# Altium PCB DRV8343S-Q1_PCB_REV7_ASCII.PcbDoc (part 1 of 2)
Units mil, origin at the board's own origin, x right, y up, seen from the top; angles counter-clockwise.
Board outline 3860 x 4000 mil, 4 copper layers (Top Layer, POWER, GND, Bottom Layer), stack 40 mil thick; 195 components, 122 nets, 548 pads, 642 vias.
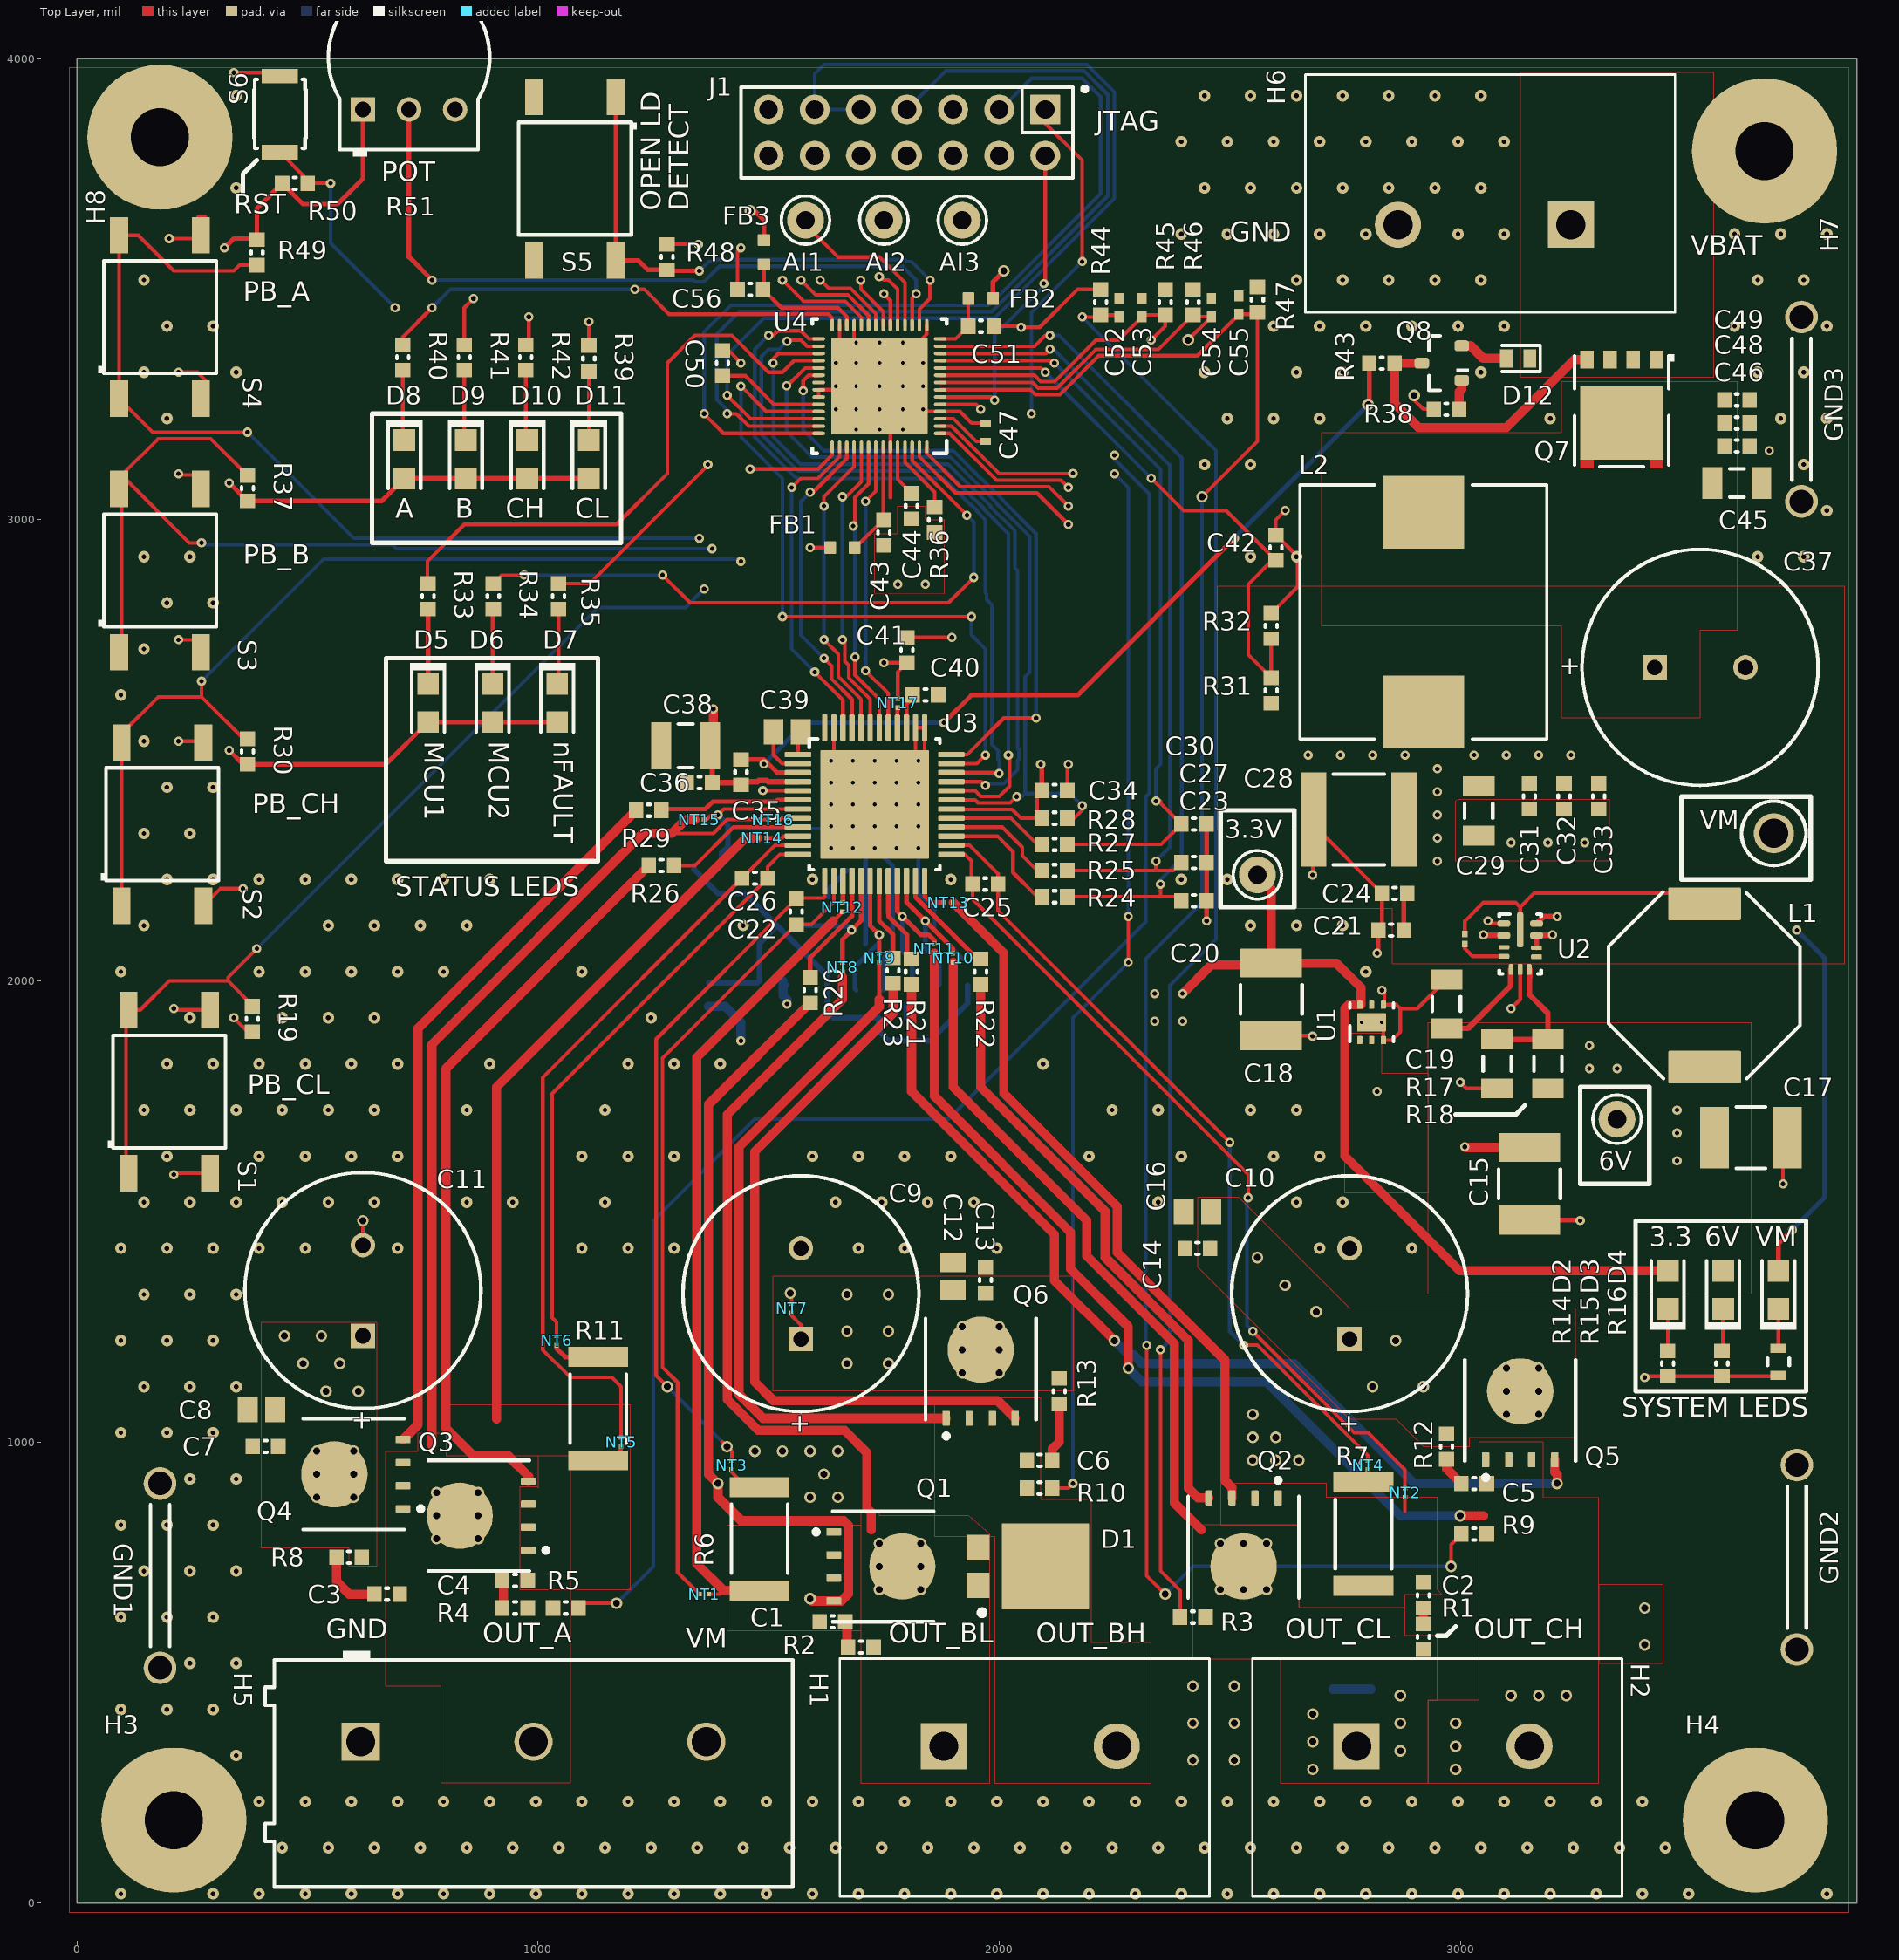
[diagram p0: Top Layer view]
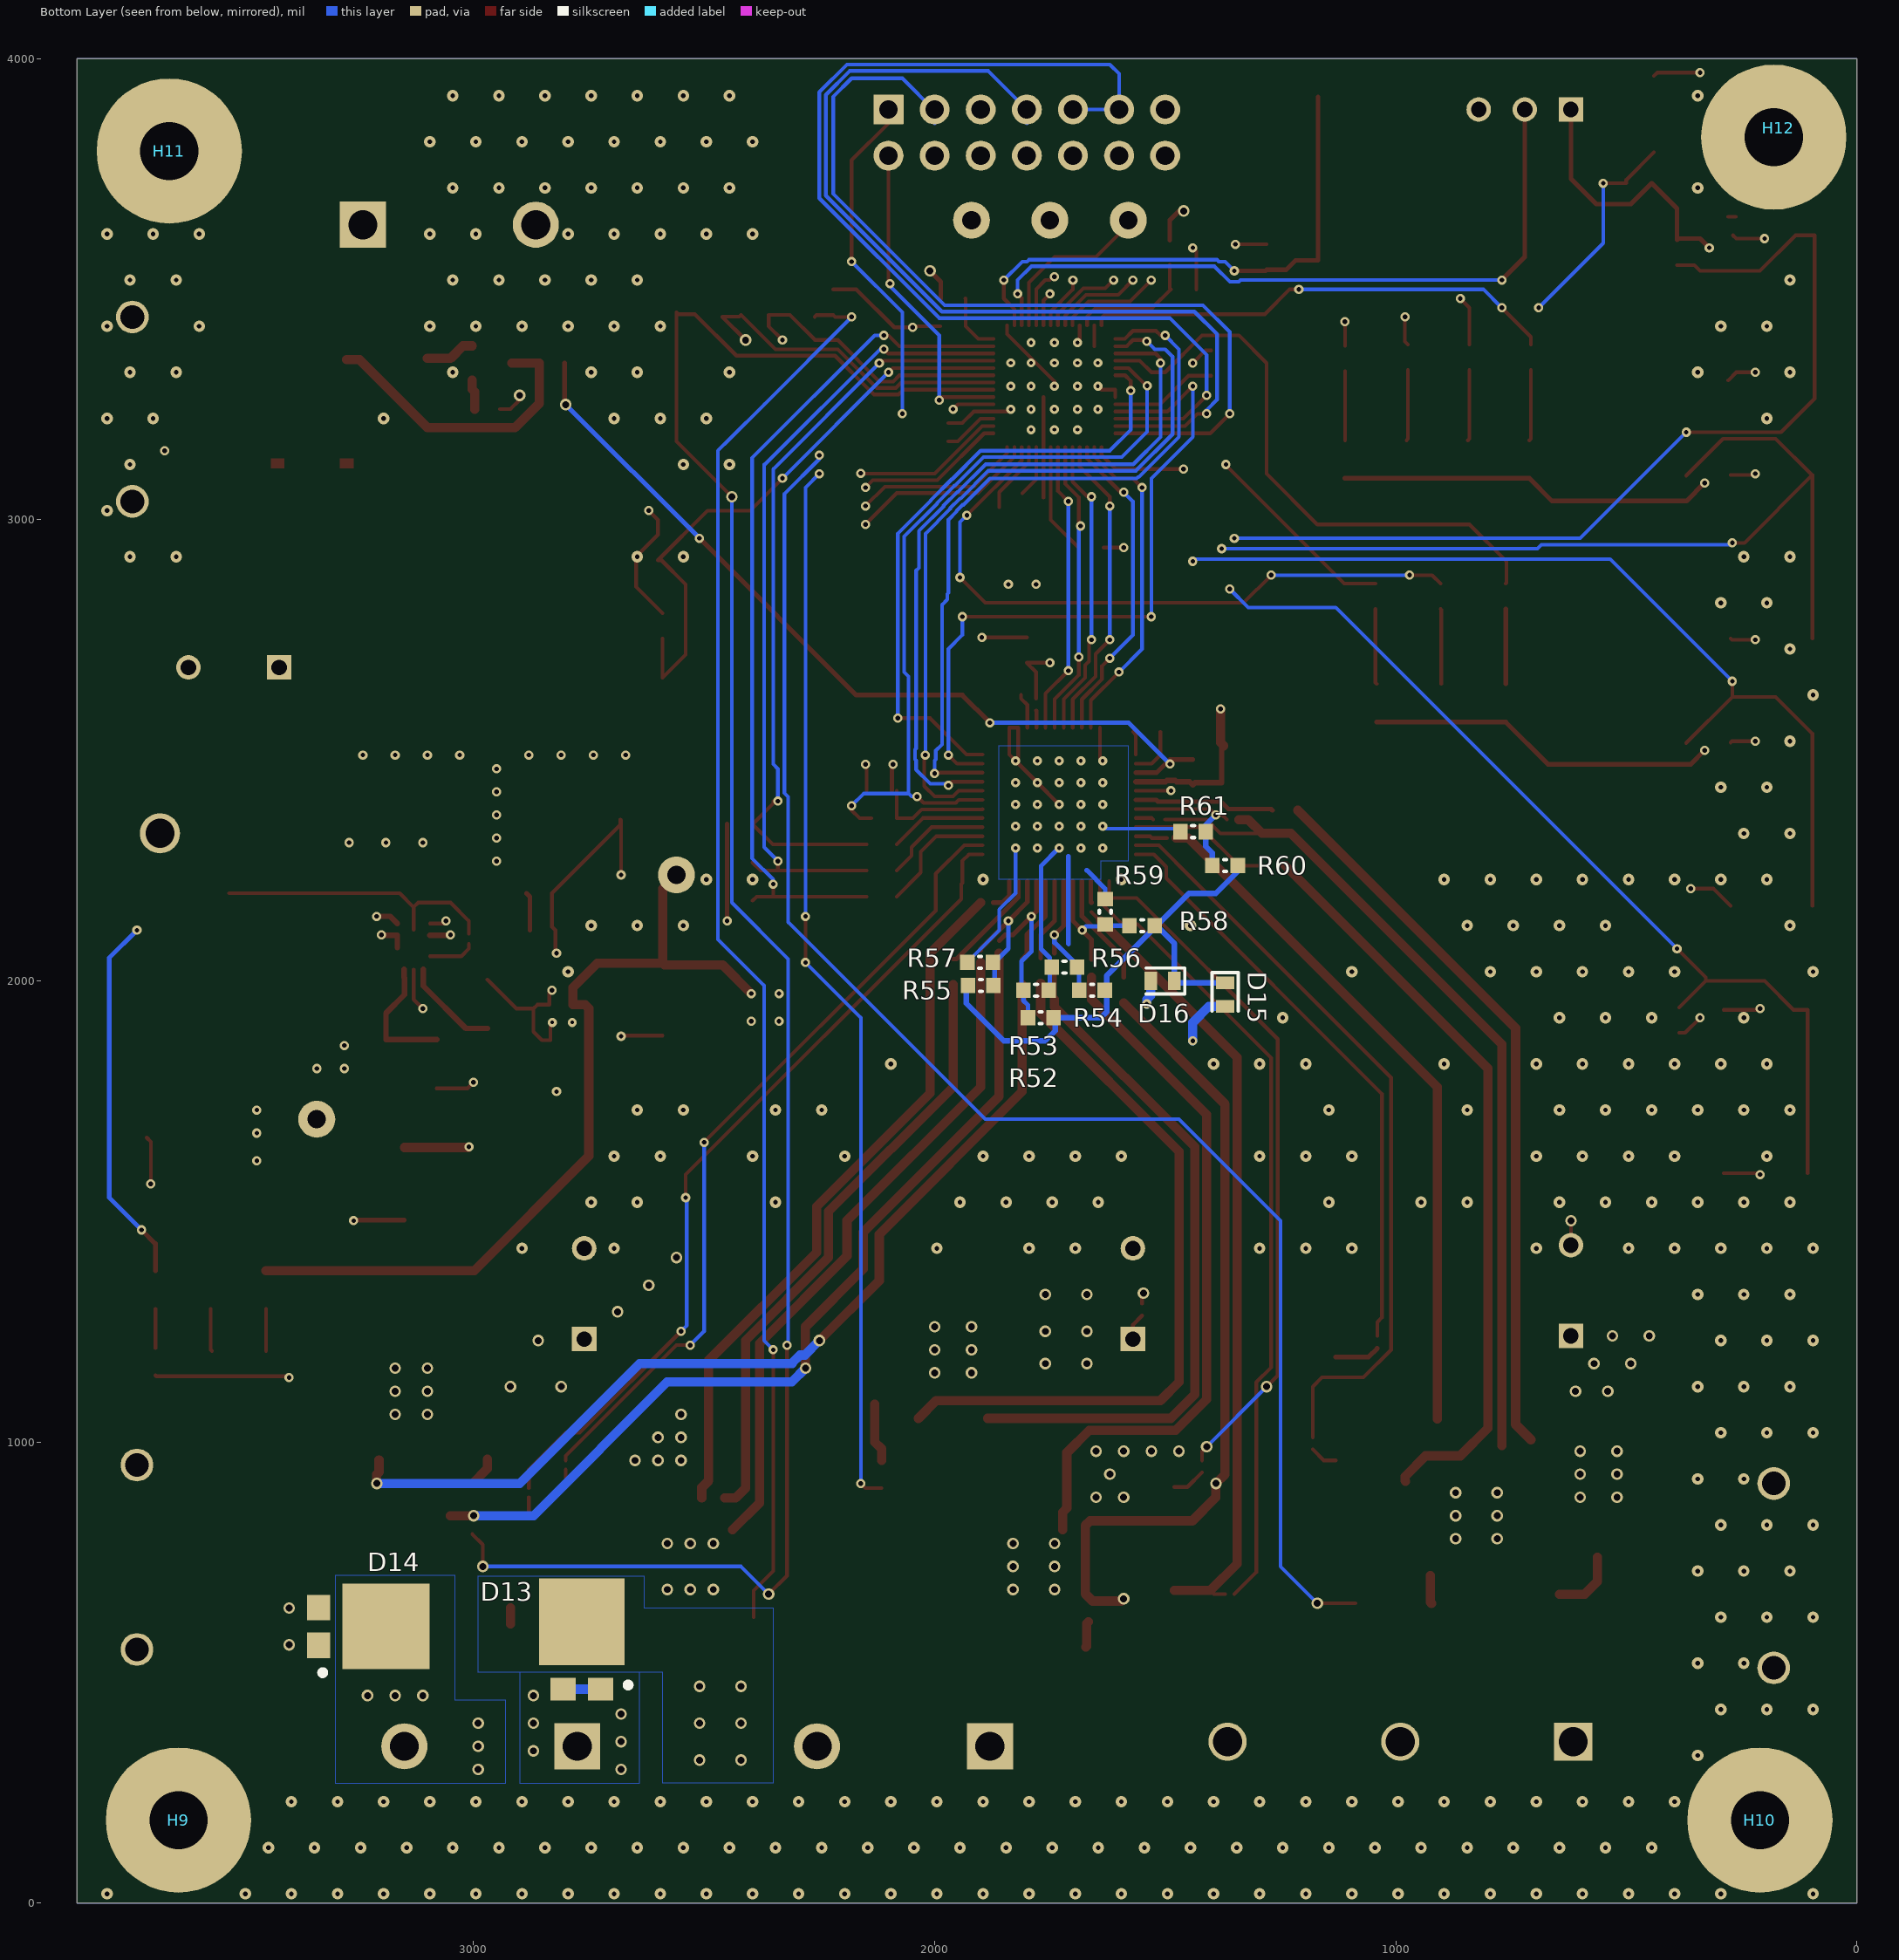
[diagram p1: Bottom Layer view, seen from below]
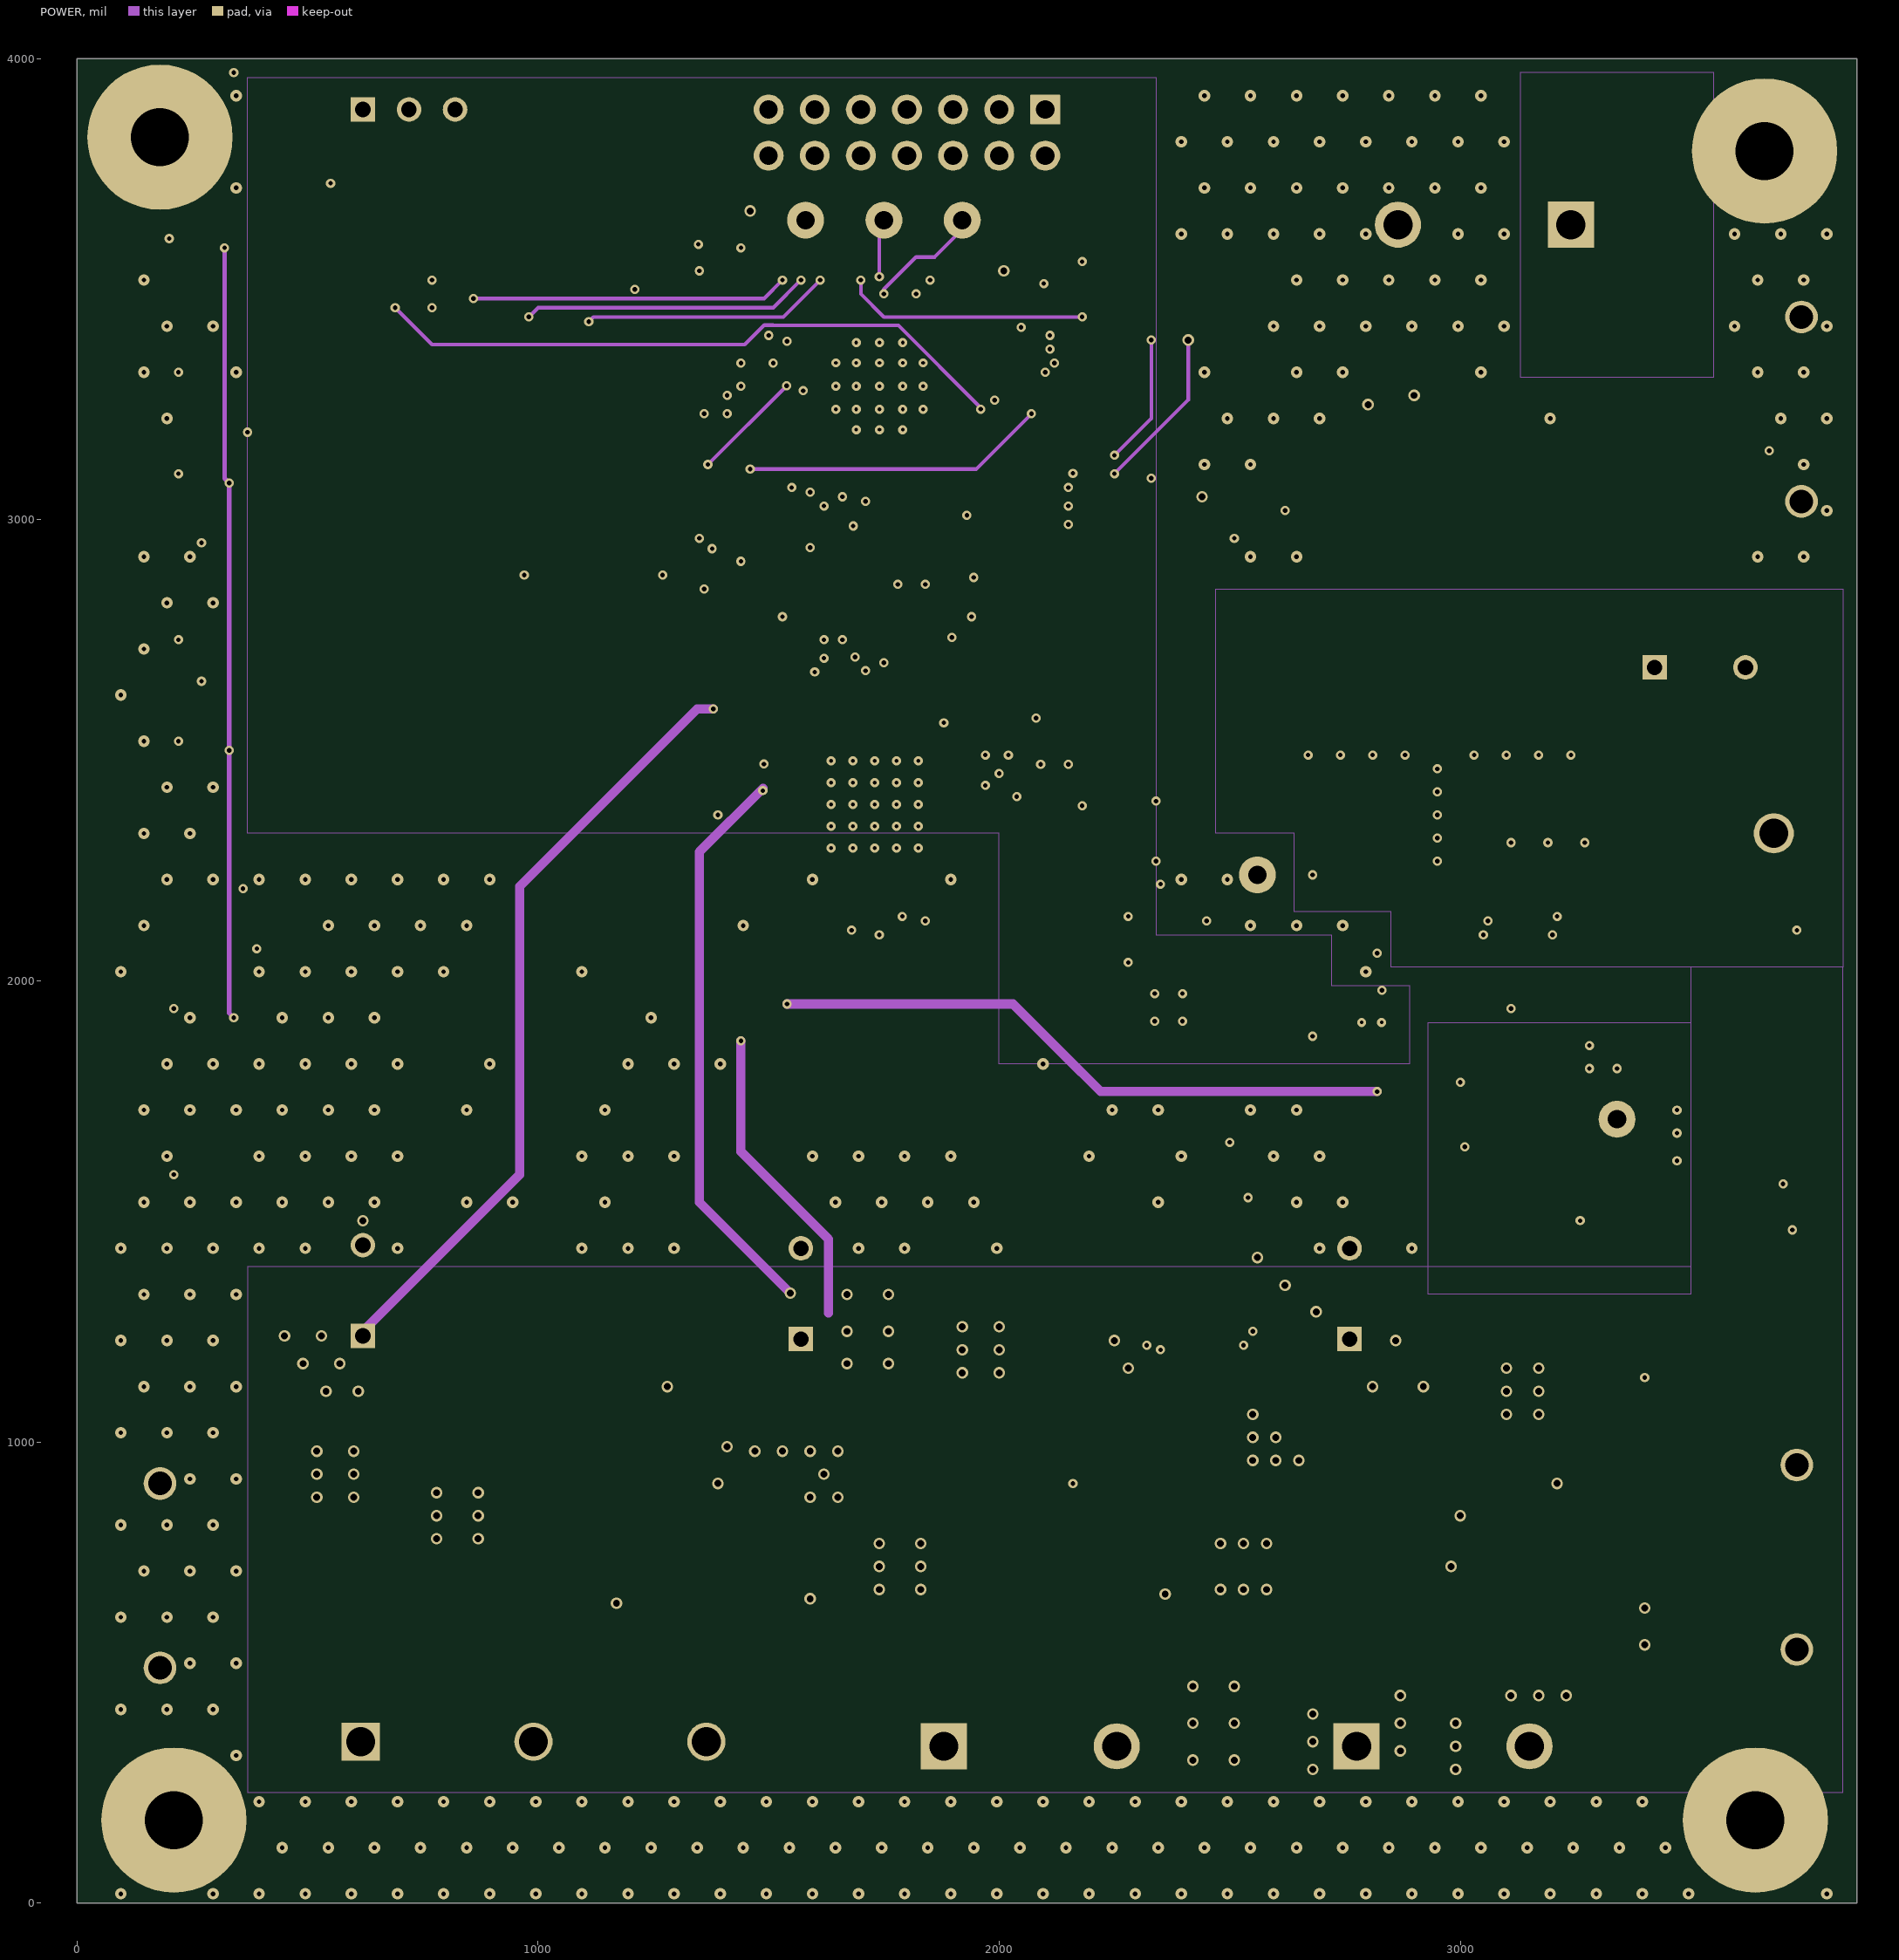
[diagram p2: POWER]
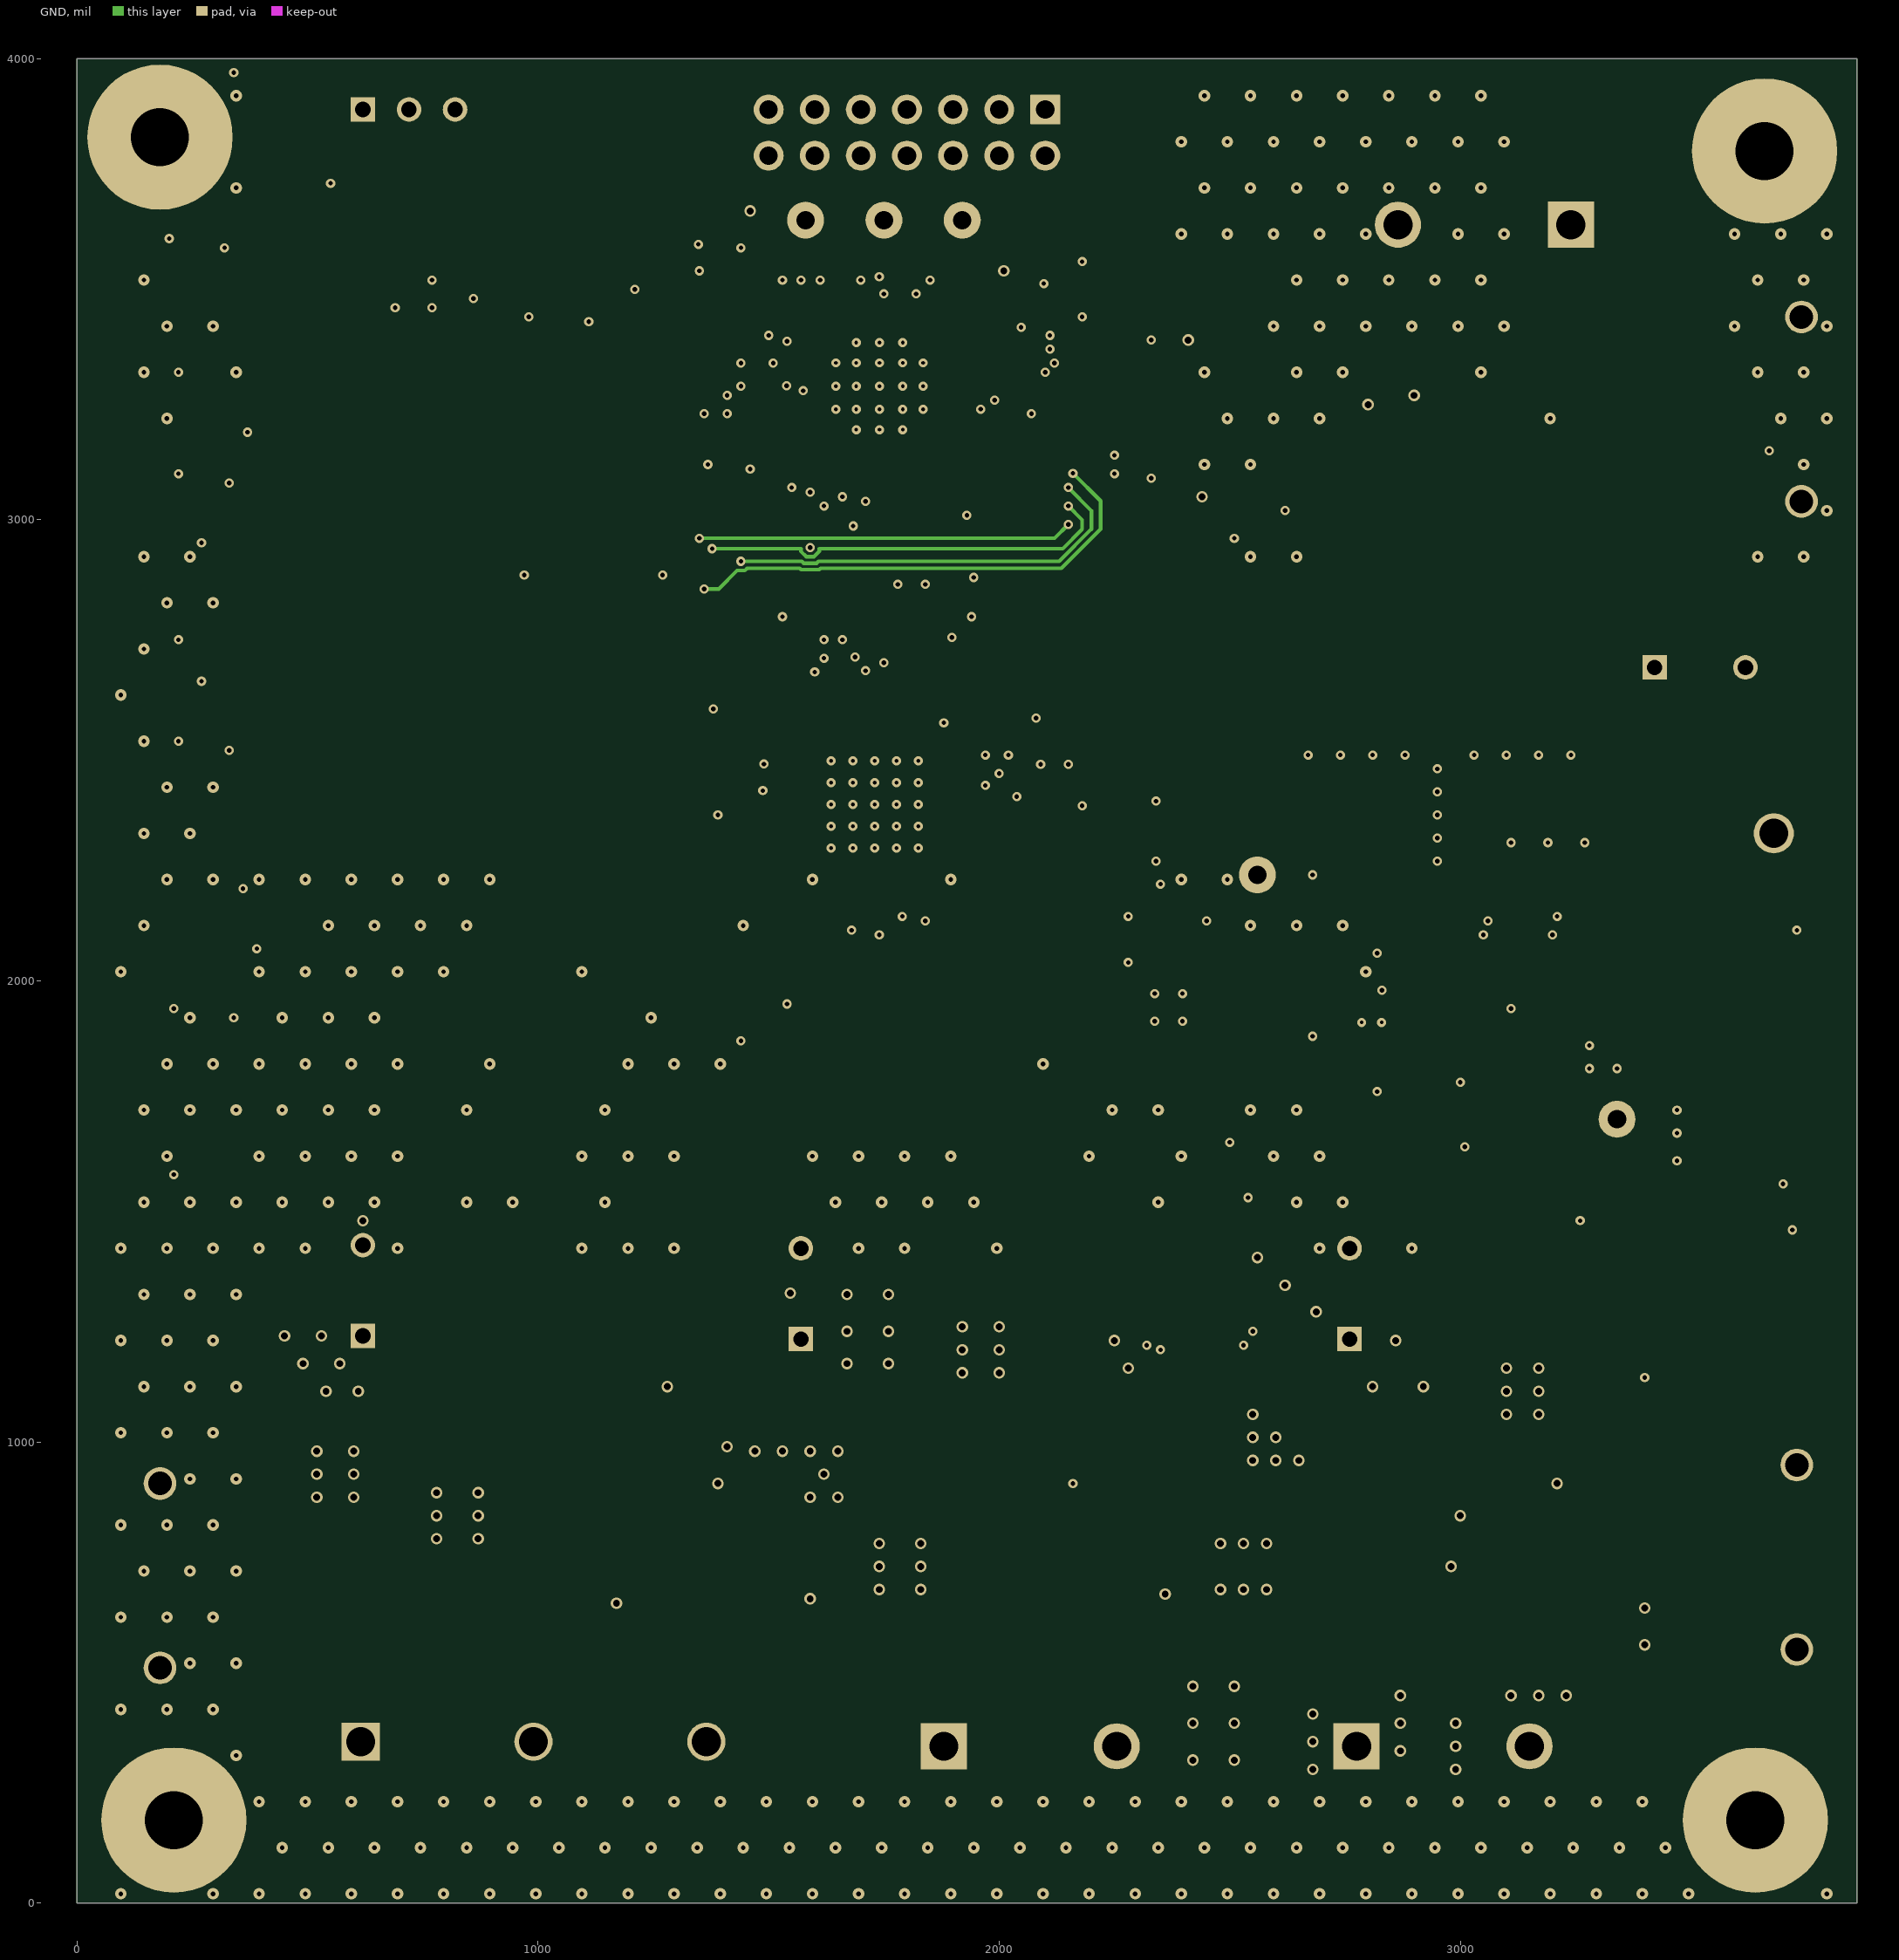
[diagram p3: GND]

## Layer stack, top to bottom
Top Solder: solder mask 0.4, Solder Resist, Dk 3.5
Top Layer: signal copper 1.4
Dielectric 1: prepreg 5, FR-4, Dk 4.2
POWER: signal copper 1.4
Dielectric 2: core 24.4, FR-4, Dk 4.2
GND: signal copper 1.4
Dielectric 3: prepreg 5, FR-4, Dk 4.2
Bottom Layer: signal copper 1.4
Bottom Solder: solder mask 0.4, Solder Resist, Dk 3.5

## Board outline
0,0 0,4000 3860,4000 3860,0

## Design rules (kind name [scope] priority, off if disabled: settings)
AssemblyTestPointUsage [All] p0 off: scope1count=1 scope1_0_kind=Board scope1_0_value=Board scope2count=1 scope2_0_kind=Board scope2_0_value=Board commentlength=0
AssemblyTestPointUsage [All] p1 off:
AssemblyTestpoint [All] p0 off: scope1count=1 scope1_0_kind=Board scope1_0_value=Board scope2count=1 scope2_0_kind=Board scope2_0_value=Board commentlength=0
AssemblyTestpoint [All] p1 off: testpointundercomponent=TRUE minsize=40 maxsize=100 preferedsize=60 minholesize=0 maxholesize=40 preferedholesize=32 testpointgrid=1 usegrid=TRUE gridtolerance=0.01 allowsidetop=TRUE allowsidebottom=TRUE
Clearance [All] p0: scope1count=1 scope1_0_kind=Board scope1_0_value=Board scope2count=1 scope2_0_kind=Board scope2_0_value=Board commentlength=0 gap=6
Clearance [All] p1: gap=6 ignorepadtopadclearanceinfootprint=FALSE except(0: Arc-Hole Track-Hole SMDPad-Hole THPad-Hole Via-Hole Fill-Hole Poly-Hole Region-Hole Text-Hole)
ComponentClearance [All] p0 off: scope1count=1 scope1_0_kind=Board scope1_0_value=Board scope2count=1 scope2_0_kind=Board scope2_0_value=Board commentlength=0 gap=10 collisioncheckmode=3
ComponentClearance [All] p1 off: gap=10 collisioncheckmode=3 verticalgap=10 showdistances=FALSE
DiffPairsRouting [All] p0 off: scope1count=1 scope1_0_kind=Board scope1_0_value=Board scope2count=1 scope2_0_kind=Board scope2_0_value=Board commentlength=0
DiffPairsRouting [All] p1 off: maxlimit=10 minlimit=10 mostfreqgap=10 toplayer_minwidth=15 toplayer_maxwidth=15 toplayer_prefwidth=15 midlayer1_minwidth=15 midlayer1_maxwidth=15 midlayer1_prefwidth=15 midlayer2_minwidth=15 midlayer2_maxwidth=15 midlayer2_prefwidth=15 bottomlayer_minwidth=15 bottomlayer_maxwidth=15 bottomlayer_prefwidth=15 maxuncoupledlength=500
FabricationTestPointUsage TestPointUsage [All] p0 off: scope1count=1 scope1_0_kind=Board scope1_0_value=Board scope2count=1 scope2_0_kind=Board scope2_0_value=Board commentlength=0 valid=0 allowmultiple=FALSE
FabricationTestPointUsage TestPointUsage [All] p1 off: valid=0 allowmultiple=FALSE
FabricationTestpoint Testpoint [All] p0 off: scope1count=1 scope1_0_kind=Board scope1_0_value=Board scope2count=1 scope2_0_kind=Board scope2_0_value=Board commentlength=0 side=3 testpointundercomponent=TRUE minsize=40 maxsize=100 preferedsize=60 minholesize=0 maxholesize=40 preferedholesize=32 testpointgrid=1
FabricationTestpoint Testpoint [All] p1 off: side=3 testpointundercomponent=TRUE minsize=40 maxsize=100 preferedsize=60 minholesize=0 maxholesize=40 preferedholesize=32 testpointgrid=1 allowsidetop=TRUE allowsidebottom=TRUE usegrid=TRUE gridtolerance=0.01
FanoutControl Fanout_Default [All] p0 off: scope1count=1 scope1_0_kind=Board scope1_0_value=Board scope2count=1 scope2_0_kind=Board scope2_0_value=Board commentlength=30 // Fanout_Default (Default Rule)
FanoutControl Fanout_Small [All] p0 off: scope1count=1 scope1_0_kind=Board scope1_0_value=Board scope2count=1 scope2_0_kind=Board scope2_0_value=Board commentlength=84 // Protel DXP Scope 1 Expression Was: (CompPinCount < 5)   Fanout_Small (Default Rule)
FanoutControl Fanout_SOIC [All] p0 off: scope1count=1 scope1_0_kind=Board scope1_0_value=Board scope2count=1 scope2_0_kind=Board scope2_0_value=Board commentlength=71 // Protel DXP Scope 1 Expression Was: IsSOIC   Fanout_SOIC (Default Rule)
FanoutControl Fanout_LCC [All] p0 off: scope1count=1 scope1_0_kind=Board scope1_0_value=Board scope2count=1 scope2_0_kind=Board scope2_0_value=Board commentlength=69 // Protel DXP Scope 1 Expression Was: IsLCC   Fanout_LCC (Default Rule)
FanoutControl Fanout_BGA [All] p0 off: scope1count=1 scope1_0_kind=Board scope1_0_value=Board scope2count=1 scope2_0_kind=Board scope2_0_value=Board commentlength=69 // Protel DXP Scope 1 Expression Was: IsBGA   Fanout_BGA (Default Rule)
FanoutControl Fanout_BGA [IsBGA] p1 off: bgadir=Out bgaviamode=Centered fanoutstyle=Auto fanoutdirection=Alternating viagrid=1 // Fanout_BGA (Default Rule)
FanoutControl Fanout_LCC [IsLCC] p2 off: bgadir=Out bgaviamode=Centered fanoutstyle=Auto fanoutdirection=Alternating viagrid=1 // Fanout_LCC (Default Rule)
FanoutControl Fanout_SOIC [IsSOIC] p3 off: bgadir=Out bgaviamode=Centered fanoutstyle=Auto fanoutdirection=Alternating viagrid=1 // Fanout_SOIC (Default Rule)
FanoutControl Fanout_Small [(CompPinCount < 5)] p4 off: bgadir=Out bgaviamode=Centered fanoutstyle=Auto fanoutdirection=OutThenIn viagrid=1 // Fanout_Small (Default Rule)
FanoutControl Fanout_Default [All] p5 off: bgadir=Out bgaviamode=Centered fanoutstyle=Auto fanoutdirection=Alternating viagrid=1 // Fanout_Default (Default Rule)
Height [All] p0 off: scope1count=1 scope1_0_kind=Board scope1_0_value=Board scope2count=1 scope2_0_kind=Board scope2_0_value=Board commentlength=0
Height [All] p1 off: minheight=0 maxheight=1000 prefheight=500
HoleSize [All] p0: scope1count=1 scope1_0_kind=Board scope1_0_value=Board scope2count=1 scope2_0_kind=Board scope2_0_value=Board commentlength=0 absolutevalues=TRUE maxlimit=400 minlimit=7.87 maxpercent=80.000 minpercent=20.000
HoleSize [All] p1: absolutevalues=TRUE maxlimit=400 minlimit=7.87 maxpercent=80.000 minpercent=20.000
HoleToHoleClearance [All] p0: scope1count=1 scope1_0_kind=Board scope1_0_value=Board scope2count=1 scope2_0_kind=Board scope2_0_value=Board commentlength=0
HoleToHoleClearance [All] p1: gap=8 allowstackedmicrovias=TRUE
LayerPairs [All] p0 off: scope1count=1 scope1_0_kind=Board scope1_0_value=Board scope2count=1 scope2_0_kind=Board scope2_0_value=Board commentlength=0 enforce=FALSE
LayerPairs [All] p1 off: enforce=FALSE
MinimumAnnularRing [All] p0: scope1count=1 scope1_0_kind=Board scope1_0_value=Board scope2count=1 scope2_0_kind=Board scope2_0_value=Board commentlength=0 minimumring=5
MinimumAnnularRing [All] p1: minimumring=5
MinimumSolderMaskSliver [All] p0: scope1count=1 scope1_0_kind=Board scope1_0_value=Board scope2count=1 scope2_0_kind=Board scope2_0_value=Board commentlength=0
MinimumSolderMaskSliver [All] p1: minsoldermaskwidth=4
NetAntennae [All] p0: scope1count=1 scope1_0_kind=Board scope1_0_value=Board scope2count=1 scope2_0_kind=Board scope2_0_value=Board commentlength=0
PasteMaskExpansion [All] p0: scope1count=1 scope1_0_kind=Board scope1_0_value=Board scope2count=1 scope2_0_kind=Board scope2_0_value=Board commentlength=0 expansion=0
PlaneClearance [All] p0: scope1count=1 scope1_0_kind=Board scope1_0_value=Board scope2count=1 scope2_0_kind=Board scope2_0_value=Board commentlength=0 clearance=20
PlaneConnect [All] p0: scope1count=1 scope1_0_kind=Board scope1_0_value=Board scope2count=1 scope2_0_kind=Board scope2_0_value=Board commentlength=0 planeconnectstyle=Relief reliefexpansion=20 reliefentries=4 reliefconductorwidth=10 reliefairgap=10
PolygonConnect [All] p0: scope1count=1 scope1_0_kind=Board scope1_0_value=Board scope2count=1 scope2_0_kind=Board scope2_0_value=Board commentlength=0 connectstyle=Direct reliefconductorwidth=25 reliefentries=4 polygonreliefangle="90 Angle"
PolygonConnect [All] p1: connectstyle=Direct reliefconductorwidth=25 reliefentries=4 polygonreliefangle="90 Angle" airgapwidth=10
RoutingCorners [All] p0: scope1count=1 scope1_0_kind=Board scope1_0_value=Board scope2count=1 scope2_0_kind=Board scope2_0_value=Board commentlength=0 cornerstyle=45-Degree minsetback=100 maxsetback=100
RoutingLayers [All] p0: scope1count=1 scope1_0_kind=Board scope1_0_value=Board scope2count=1 scope2_0_kind=Board scope2_0_value=Board commentlength=0 top layer=Automatic mid layer 1=Automatic mid layer 2=Automatic bottom layer=Automatic
RoutingPriority [All] p0: scope1count=1 scope1_0_kind=Board scope1_0_value=Board scope2count=1 scope2_0_kind=Board scope2_0_value=Board commentlength=0
RoutingTopology [All] p0: scope1count=1 scope1_0_kind=Board scope1_0_value=Board scope2count=1 scope2_0_kind=Board scope2_0_value=Board commentlength=0 topology=Shortest
RoutingVias [All] p0: scope1count=1 scope1_0_kind=Board scope1_0_value=Board scope2count=1 scope2_0_kind=Board scope2_0_value=Board commentlength=0 holewidth=15 width=25 viastyle="Through Hole" minholewidth=7.87 minwidth=18 maxholewidth=400 maxwidth=500
RoutingVias [All] p1: holewidth=15 width=25 viastyle="Through Hole" minholewidth=7.87 minwidth=18 maxholewidth=400 maxwidth=500
ShortCircuit [All] p0: scope1count=1 scope1_0_kind=Board scope1_0_value=Board scope2count=1 scope2_0_kind=Board scope2_0_value=Board commentlength=0 allowed=FALSE
SilkToBoardRegionClearance [All] p0: scope1count=1 scope1_0_kind=Board scope1_0_value=Board scope2count=1 scope2_0_kind=Board scope2_0_value=Board commentlength=0
SilkToSilkClearance [All] p0: scope1count=1 scope1_0_kind=Board scope1_0_value=Board scope2count=1 scope2_0_kind=Board scope2_0_value=Board commentlength=0
SilkToSilkClearance [All] p1: silktosilkclearance=5
SilkToSolderMaskClearance SilkscreenOverComponentPads [All] p0 off: scope1count=1 scope1_0_kind=Board scope1_0_value=Board scope2count=1 scope2_0_kind=Board scope2_0_value=Board commentlength=44 // Protel DXP Scope 1 Expression Was: IsPad
SilkToSolderMaskClearance SilkscreenOverComponentPads [IsPad] p1: minsilkscreentomaskgap=5 clearancetoexposedcopper=TRUE
SolderMaskExpansion [All] p0: scope1count=1 scope1_0_kind=Board scope1_0_value=Board scope2count=1 scope2_0_kind=Board scope2_0_value=Board commentlength=0 expansion=2
SolderMaskExpansion [All] p1: expansion=2
UnRoutedNet [All] p0: scope1count=1 scope1_0_kind=Board scope1_0_value=Board scope2count=1 scope2_0_kind=Board scope2_0_value=Board commentlength=0
UnpouredPolygon [All] p0: scope1count=1 scope1_0_kind=Board scope1_0_value=Board scope2count=1 scope2_0_kind=Board scope2_0_value=Board commentlength=0
Width [All] p0: scope1count=1 scope1_0_kind=Board scope1_0_value=Board scope2count=1 scope2_0_kind=Board scope2_0_value=Board commentlength=0 maxlimit=50 minlimit=8 preferedwidth=8
Width [All] p1: maxlimit=50 minlimit=8 preferedwidth=8
12 further rules are at their usual default settings.

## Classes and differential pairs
component class TIDA_CONTROL: Ai0 AI2 AI3 D1 D2 D3 D5 D6 D7 D8 D9 D10 D12 D16 GND1 GND2 GND3 J1 R1 R5 R7 R11 R13 R14 R15 R26 R27 R30 R31 R32 R34 R35 R37 R48 R49 R50 R51 S1 S2 S3 S4 S5 S6 U3

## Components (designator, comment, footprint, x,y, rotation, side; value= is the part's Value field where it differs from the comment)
3.3V "5000" Keystone5000 2560,2230 r90 top (schematic designator TP7)
6V "5000" Keystone5000 3340,1700 r90 top (schematic designator TP13)
AI1 "" Keystone5002 1580,3650 r90 top (schematic designator TP1)
AI2 "" Keystone5002 1750,3650 r90 top (schematic designator TP2)
AI3 "" Keystone5002 1920,3650 r90 top (schematic designator TP3)
C1 "GRM188R72A103KA01D" 0603L 1638.59,609.92 r180 top (schematic designator C52)
C2 "GRM188R72A103KA01D" 0603L 2920,667.56 r90 top (schematic designator C51)
C3 "GRM188R72A103KA01D" 0603L 672.44,670 r0 top (schematic designator C49)
C4 "GRM188R72A103KA01D" 0603L 950,700 r0 top (schematic designator C50)
C5 "GRM188R72A103KA01D" 0603L 3030,910 r0 top (schematic designator C48)
C6 "GRM188R72A103KA01D" 0603L 2087.56,960 r180 top (schematic designator C47)
C7 "06031C103JAT2A" 0603L 408.86,990 r180 top (schematic designator C39)
C8 "CGA4J3X7S2A105K125AB" 0805L 400,1070 r180 top (schematic designator C38)
C9 "ELXZ630ELL331MK20S" Chemi-Con_1250x2000 1570,1321.57 r90 top (schematic designator C45)
C10 "ELXZ630ELL331MK20S" Chemi-Con_1250x2000 2760,1321.57 r90 top (schematic designator C46)
C11 "ELXZ630ELL331MK20S" Chemi-Con_1250x2000 620,1328.43 r90 top (schematic designator C44)
C12 "CGA4J3X7S2A105K125AB" 0805L 1900,1360 r90 top (schematic designator C40)
C13 "06031C103JAT2A" 0603L 1970,1351.14 r90 top (schematic designator C41)
C14 "06031C103JAT2A" 0603L 2430,1420 r180 top (schematic designator C43)
C15 "CGA8N3X7R1C226M230KB" 1812_254 3150,1560 r270 top (schematic designator C28)
C16 "CGA4J3X7S2A105K125AB" 0805L 2430,1500 r180 top (schematic designator C42)
C17 "CGA8N3X7R1C226M230KB" 1812_254 3630,1660 r0 top (schematic designator C33)
C18 "CGA8N3X7R1C226M230KB" 1812_254 2590,1960 r270 top (schematic designator C29)
C19 "CGA5L2X7R2A105K160AA" 1206_180L 2970,1950 r90 top (schematic designator C34)
C20 "GCM033R71E101KA03D" 0201_033L 3010,2091.02 r90 top (schematic designator C27)
C21 "CGA3E2X7R2A223K080AA" 0603L 2850,2110 r180 top (schematic designator C32)
C22 "GRM188R71C102KA01D" 0603L 1560,2150.31 r90 top (schematic designator C55)
C23 "GRM188R71C222KA01D" 0603L 2422.44,2173.91 r0 top (schematic designator C8)
C24 "CGA3E2X7R2A223K080AA" 0603L 2857.56,2190 r180 top (schematic designator C31)
C25 "GRM188R71C102KA01D" 0603L 1970,2210 r0 top (schematic designator C54)
C26 "GRM188R71C102KA01D" 0603L 1470,2222.76 r0 top (schematic designator C53)
C27 "GRM188R71C222KA01D" 0603L 2422.44,2256.96 r0 top (schematic designator C9)
C28 "CGA9N2X7R2A475K230KA" 2220_250L 2780,2350 r180 top (schematic designator C30)
C29 "GCM31CR72A105KA03" 1206_180L 3040,2368.5 r270 top (schematic designator C23)
C30 "GRM188R71C222KA01D" 0603L 2422.44,2340 r0 top (schematic designator C10)
C31 "CGA3E3X7S2A104K080AB" 0603L 3150,2400 r270 top (schematic designator C22)
C32 "CGA3E2X7R2A103K080AA" 0603L 3225,2400 r270 top (schematic designator C21)
C33 "CGA3E2X7R2A102K080AA" 0603L 3300,2400 r270 top (schematic designator C20)
C34 "GRM188R70J104KA01D" 0603L 2120,2412.76 r0 top (schematic designator C7)
C35 "GCM188R71E105KA64D" 0603L 1440,2452.76 r90 top (schematic designator C1)
C36 "GCJ188R72A104KA01D" 0603L 1350,2430 r180 top (schematic designator C3)
C37 "ELXZ630ELL331MK20S" Chemi-Con_1250x2000 3520,2680 r0 top (schematic designator C15)
C38 "GRM32ER71K475KE14L" 1210_270L 1320,2510 r180 top (schematic designator C2)
C39 "CGA4J2X7R2A473K125AA" 0805L 1540,2540 r0 top (schematic designator C4)
C40 "C0603C105K9RACAUTO" 0603L 1840,2620 r0 top (schematic designator C5)
C41 "CGJ3E2X7R1C104K080AA" 0603L 1800,2717.56 r90 top (schematic designator C6)
C42 "C0603C104J4RACTU" 0603L 2600,2940 r90 top (schematic designator C25)
C43 "GRM188R71A225KE15D" 0603L 1750,2972.44 r270 top (schematic designator C26)
C44 "GRM188R71A225KE15D" 0603L 1810,3030 r270 top (schematic designator C13)
C45 "GCM31CR72A105KA03" 1206_180L 3600,3080 r0 top (schematic designator C16)
C46 "CGA3E3X7S2A104K080AB" 0603L 3600,3160 r0 top (schematic designator C17)
C47 "GRT155C71A225KE13" 0402_070 1970,3190 r90 top (schematic designator C11)
C48 "CGA3E2X7R2A103K080AA" 0603L 3600,3210 r0 top (schematic designator C18)
C49 "CGA3E2X7R2A102K080AA" 0603L 3600,3260 r0 top (schematic designator C19)
C50 "GRM188R71A225KE15D" 0603L 1400,3340 r90 top (schematic designator C12)
C51 "GRM188R71A225KE15D" 0603L 1960.39,3420 r0 top (schematic designator C14)
C52 "C0402C104K4RACAUTO" 0402L 2260,3460.31 r90 top (schematic designator C56)
C53 "C0402C104K4RACAUTO" 0402L 2310,3460.31 r90 top (schematic designator C35)
C54 "C0402C104K4RACAUTO" 0402L 2460,3460.31 r90 top (schematic designator C36)
C55 "C0402C104K4RACAUTO" 0402L 2520,3465.75 r90 top (schematic designator C37)
C56 "GRM188R71A225KE15D" 0603L 1460,3500 r180 top (schematic designator C24)
D1 "FSV20100V" TO-277A 2025.89,730 r90 top (schematic designator D14)
D2 "LTST-C170KGKT" LTST-C170KGKT_Green 3450,1330 r270 top (schematic designator D5)
D3 "LTST-C170KGKT" LTST-C170KGKT_Green 3570,1330 r270 top
D4 "LTST-C170KGKT" LTST-C170KGKT_Green 3690,1330 r270 top (schematic designator D1)
D5 "LTST-C170KFKT" LTST-C170KFKT_Orange 761.37,2602.85 r90 top (schematic designator D9)
D6 "LTST-C170KFKT" LTST-C170KFKT_Orange 901.37,2602.85 r90 top (schematic designator D10)
D7 "LTST-C170KRKT" LED_LTST-C170_Red 1041.37,2602.85 r90 top
D8 "LTST-C170KFKT" LTST-C170KFKT_Orange 710,3131.34 r90 top (schematic designator D2)
D9 "LTST-C170KFKT" LTST-C170KFKT_Orange 843.33,3131.34 r90 top (schematic designator D4)
D10 "LTST-C170KFKT" LTST-C170KFKT_Orange 976.67,3131.34 r90 top (schematic designator D6)
D11 "LTST-C170KFKT" LTST-C170KFKT_Orange 1110,3131.34 r90 top (schematic designator D8)
D12 "CD0603-S0180" Diode_0603 3125.59,3350 r180 top
D13 "FSV20100V" TO-277A 2765.22,535.89 r0 bottom
D14 "FSV20100V" TO-277A 3264.11,600 r90 bottom (schematic designator D15)
D15 "CD0603-S0180" Diode_0603 1370,1970 r270 bottom (schematic designator D16)
D16 "CD0603-S0180" Diode_0603 1505.59,2000 r0 bottom (schematic designator D11)
FB1 "BLM18PG331SH1" FP-BLM18PG331SH1_0603-Recommended_Land_Pattern 1660,2940 r0 top (schematic designator FB3)
FB2 "BLM18PG331SH1" FP-BLM18PG331SH1_0603-Recommended_Land_Pattern 1960,3480 r180 top (schematic designator FB1)
FB3 "BLM18PG331SH1" FP-BLM18PG331SH1_0603-Recommended_Land_Pattern 1490,3580 r270 top (schematic designator FB2)
GND1 "D3082-05" Harwin_D3082-05 180,710 r90 top (schematic designator GND3)
GND2 "D3082-05" Harwin_D3082-05 3730,750 r90 top (schematic designator GND1)
GND3 "D3082-05" Harwin_D3082-05 3740,3240 r90 top (schematic designator GND2)
H1 "OSTT7022150" TERM_BLK_OSTT7022150 1880,340 r0 top (schematic designator H2)
H2 "OSTT7022150" TERM_BLK_OSTT7022150 2775,340 r0 top (schematic designator H3)
H3 "NY PMS 440 0025 PH" "NY PMS 440 0025 PH" 210,180 r0 top (schematic designator H7)
H4 "NY PMS 440 0025 PH" "NY PMS 440 0025 PH" 3640,180 r0 top (schematic designator H6)
H5 "OSTT7032150" On-Shore_OSTT7032150 990,350 r0 top (schematic designator H4)
H6 "OSTT7022150" TERM_BLK_OSTT7022150 3240,3640 r180 top (schematic designator H1)
H7 "NY PMS 440 0025 PH" "NY PMS 440 0025 PH" 3660,3800 r0 top (schematic designator H5)
H8 "NY PMS 440 0025 PH" "NY PMS 440 0025 PH" 180,3830 r0 top
H9 "1902C" Keystone_1902C 3640.36,180 r180 bottom (schematic designator H10)
H10 "1902C" Keystone_1902C 210.36,180 r180 bottom (schematic designator H11)
H11 "1902C" Keystone_1902C 3660.36,3800 r180 bottom (schematic designator H9)
H12 "1902C" Keystone_1902C 170.36,3850 r180 bottom
J1 "TSW-107-07-G-D" TSW-107-07-X-D 1800,3840 r180 top
L1 "SRU1028A-470Y" SRU1028A 3530,1990 r270 top (schematic designator L2)
L2 "SRP1250-1R0M" SRP1250 2920,2800 r270 top (schematic designator L1)
NT1 "Net-Tie" Net-Tie_10mil 1360,670 r0 top net-tie (schematic designator NT13)
NT2 "Net-Tie" Net-Tie_10mil 2880,890 r270 top net-tie (schematic designator NT12)
NT3 "Net-Tie" Net-Tie_10mil 1420,950 r270 top net-tie (schematic designator NT16)
NT4 "Net-Tie" Net-Tie_10mil 2800,950 r270 top net-tie (schematic designator NT15)
NT5 "Net-Tie" Net-Tie_10mil 1180,1000 r270 top net-tie (schematic designator NT11)
NT6 "Net-Tie" Net-Tie_10mil 1040,1220 r270 top net-tie (schematic designator NT14)
NT7 "Net-Tie" Net-Tie_10mil 1550,1290 r90 top net-tie (schematic designator NT1)
NT8 "Net-Tie" Net-Tie_10mil 1660,2030 r270 top net-tie (schematic designator NT7)
NT9 "Net-Tie" Net-Tie_10mil 1740,2050 r270 top net-tie (schematic designator NT3)
NT10 "Net-Tie" Net-Tie_10mil 1900,2050 r270 top net-tie (schematic designator NT6)
NT11 "Net-Tie" Net-Tie_10mil 1860,2070 r270 top net-tie (schematic designator NT2)
NT12 "Net-Tie" Net-Tie_10mil 1660,2159.76 r270 top net-tie (schematic designator NT10)
NT13 "Net-Tie" Net-Tie_10mil 1890,2170 r0 top net-tie (schematic designator NT9)
NT14 "Net-Tie" Net-Tie_10mil 1486,2310 r180 top net-tie (schematic designator NT8)
NT15 "Net-Tie" Net-Tie_10mil 1350,2350 r180 top net-tie (schematic designator NT4)
NT16 "Net-Tie" Net-Tie_10mil 1510,2350 r180 top net-tie (schematic designator NT5)
NT17 "Net-Tie" Net-Tie_10mil 1780,2602.76 r270 top net-tie
Q1 "SQJ850EP-T1-GE3" FP-SQJ850EP-T1-GE3_PowerPAK-SO-8L-Single-MFG 1748.24,730 r270 top (schematic designator Q8)
Q2 "SQJ850EP-T1-GE3" FP-SQJ850EP-T1-GE3_PowerPAK-SO-8L-Single-MFG 2530,771.76 r180 top (schematic designator Q7)
Q3 "SQJ850EP-T1-GE3" FP-SQJ850EP-T1-GE3_PowerPAK-SO-8L-Single-MFG 871.76,840 r90 top (schematic designator Q6)
Q4 "SQJ850EP-T1-GE3" FP-SQJ850EP-T1-GE3_PowerPAK-SO-8L-Single-MFG 600,930 r90 top (schematic designator Q3)
Q5 "SQJ850EP-T1-GE3" FP-SQJ850EP-T1-GE3_PowerPAK-SO-8L-Single-MFG 3130,1068.24 r0 top
Q6 "SQJ850EP-T1-GE3" FP-SQJ850EP-T1-GE3_PowerPAK-SO-8L-Single-MFG 1960,1158.24 r0 top (schematic designator Q4)
Q7 "NVMFS6H818NWFT1G" SO-8FL 3350,3237.46 r270 top (schematic designator Q2)
Q8 "FMMT620TA" SOT-23L 2960,3340 r180 top (schematic designator Q1)
R1 "CRCW0603100RJNEA" 0603L 2920,577.56 r270 top (schematic designator R46)
R2 "CRCW0603100RJNEA" 0603L 1700,555 r0 top (schematic designator R49)
R3 "CRCW060393K1FKEA" 0603L 2420,620 r0 top (schematic designator R54)
R4 "CRCW0603100RJNEA" 0603L 950,640 r0 top (schematic designator R45)
R5 "CRCW060393K1FKEA" 0603L 1060,640 r180 top (schematic designator R33)
R6 "PMR100HZPFU5L00" 2512L 1480,790 r270 top (schematic designator R53)
R7 "PMR100HZPFU5L00" 2512L 2790,800 r270 top (schematic designator R52)
R8 "CRCW0603100RJNEA" 0603L 590,750 r0 top (schematic designator R39)
R9 "CRCW060393K1FKEA" 0603L 3030,800 r0 top (schematic designator R35)
R10 "CRCW060393K1FKEA" 0603L 2087.56,900 r180 top (schematic designator R34)
R11 "PMR100HZPFU5L00" 2512L 1130,1072.2 r270 top (schematic designator R51)
R12 "CRCW0603100RJNEA" 0603L 2970,990 r90 top (schematic designator R41)
R13 "CRCW0603100RJNEA" 0603L 2130,1110 r90 top (schematic designator R40)
R14 "CRCW0603330RJNEA" 0603L 3450,1170 r90 top (schematic designator R8)
R15 "RG1608P-471-B-T5" 0603L 3567.54,1170 r90 top (schematic designator R3)
R16 "TNPW06035K11BEEA" TNPW0603 3690,1173.94 r270 top (schematic designator R1)
R17 "CRCW120620K0FKEA" 1206L 3080,1820 r90 top (schematic designator R32)
R18 "TNPW1206100KBEEA" 1206L 3190,1820 r270 top (schematic designator R31)
R19 "CRCW060347K0FKEA" 0603L 380,1917.56 r270 top (schematic designator R16)
R20 "CRCW06030000Z0EA" 0603L 1590,1980 r270 top (schematic designator R50)
R21 "CRCW06030000Z0EA" 0603L 1810,2020 r270 top (schematic designator R44)
R22 "CRCW06030000Z0EA" 0603L 1960,2020 r270 top (schematic designator R48)
R23 "CRCW06030000Z0EA" 0603L 1770,2022.44 r270 top (schematic designator R43)
R24 "CRCW060356R0JNEA" 0603L 2120,2182.76 r180 top
R25 "CRCW060356R0JNEA" 0603L 2120,2239.42 r180 top
R26 "CRCW06030000Z0EA" 0603L 1267.56,2250 r180 top (schematic designator R47)
R27 "CRCW060356R0JNEA" 0603L 2120,2296.09 r180 top (schematic designator R26)
R28 "CRCW060310K0JNEA" 0603L 2120,2352.76 r180 top (schematic designator R23)
R29 "CRCW06030000Z0EA" 0603L 1240,2370 r180 top (schematic designator R42)
R30 "CRCW060347K0FKEA" 0603L 370,2497.56 r270 top (schematic designator R15)
R31 "CRCW060393K1FKEA" 0603L 2590,2630 r270 top (schematic designator R29)
R32 "CR0603-FX-4991ELF" 0603L 2590,2770 r270 top (schematic designator R30)
R33 "CRCW0603330RJNEA" 0603L 761.37,2834.19 r270 top (schematic designator R17)
R34 "CRCW0603330RJNEA" 0603L 902.73,2834.19 r270 top (schematic designator R18)
R35 "CRCW0603330RJNEA" 0603L 1044.1,2834.19 r270 top (schematic designator R11)
R36 "CRCW06030000Z0EA" 0603L 1860,3000 r90 top (schematic designator R7)
R37 "CRCW060347K0FKEA" 0603L 370,3068.5 r270 top (schematic designator R14)
R38 "CRCW060310K0JNEA" 0603L 2970,3240 r180 top (schematic designator R28)
R39 "CRCW0603330RJNEA" 0603L 1110,3350 r270 top (schematic designator R12)
R40 "CRCW0603330RJNEA" 0603L 706.67,3352.44 r270 top (schematic designator R2)
R41 "CRCW0603330RJNEA" 0603L 840,3352.44 r270 top (schematic designator R4)
R42 "CRCW0603330RJNEA" 0603L 973.33,3352.44 r270 top (schematic designator R9)
R43 "CRCW060310K0JNEA" 0603L 2830,3340 r0 top (schematic designator R27)
R44 "CR0603-FX-4991ELF" 0603L 2220,3472.12 r270 top (schematic designator R55)
R45 "CR0603-FX-4991ELF" 0603L 2360,3472.12 r270 top (schematic designator R36)
R46 "CR0603-FX-4991ELF" 0603L 2420,3472.12 r270 top (schematic designator R37)
R47 "CR0603-FX-4991ELF" 0603L 2560,3477.56 r270 top (schematic designator R38)
R48 "CRCW060347K0FKEA" 0603L 1280,3570 r90 top (schematic designator R6)
R49 "CRCW060347K0FKEA" 0603L 390,3580 r90 top (schematic designator R13)
R50 "CRCW060347K0FKEA" 0603L 472.44,3730 r180 top (schematic designator R5)
R51 "3352T-1-503LF" Bourns_3352T 720,3890 r0 top (schematic designator R10)
R52 "CRCW060347K0FKEA" 0603L 1770,1920 r180 bottom (schematic designator R58)
R53 "CRCW060347K0FKEA" 0603L 1780,1980 r0 bottom (schematic designator R59)
R54 "CRCW060347K0FKEA" 0603L 1658.5,1980 r180 bottom (schematic designator R20)
R55 "CRCW060347K0FKEA" 0603L 1900,1990 r0 bottom (schematic designator R60)
R56 "CRCW060347K0FKEA" 0603L 1718.5,2030 r180 bottom (schematic designator R22)
R57 "CRCW060347K0FKEA" 0603L 1901.5,2040 r180 bottom (schematic designator R61)
R58 "CRCW060347K0FKEA" 0603L 1550,2120 r180 bottom (schematic designator R56)
R59 "CRCW060347K0FKEA" 0603L 1630,2150 r270 bottom (schematic designator R57)
R60 "CRCW060347K0FKEA" 0603L 1370,2250 r180 bottom (schematic designator R19)
R61 "CRCW060347K0FKEA" 0603L 1439.4,2323.74 r180 bottom (schematic designator R21)
S1 "1138K9-9F9F1125" SW_1138K9-9F9F1125 200,1760 r90 top (schematic designator S6)
S2 "1138K9-9F9F1125" SW_1138K9-9F9F1125 185,2340 r90 top (schematic designator S5)
S3 "1138K9-9F9F1125" SW_1138K9-9F9F1125 180,2890 r90 top (schematic designator S4)
S4 "1138K9-9F9F1125" SW_1138K9-9F9F1125 180,3440 r90 top (schematic designator S3)
S5 "1138K9-9F9F1125" SW_1138K9-9F9F1125 1080,3740 r270 top (schematic designator S2)
S6 "SKRKAEE010" SW_SKRKAEE010 440,3880 r90 top (schematic designator S1)
U1 "TPS7B8133QDRVRQ1" DRV0006A 2807.72,1910 r90 top (schematic designator U4)
U2 "LMR36006AQRNXRQ1" RNX0012A 3130,2080 r0 top (schematic designator U3)
U3 "DRV8343SPHPQ1" PHP0048G_N 1730,2382.76 r0 top (schematic designator U2)
U4 "TMS320F28035RSHS" RSH0056D 1740.39,3290 r180 top (schematic designator U1)
VM "5005" Keystone5005 3680,2320 r90 top (schematic designator TP4)

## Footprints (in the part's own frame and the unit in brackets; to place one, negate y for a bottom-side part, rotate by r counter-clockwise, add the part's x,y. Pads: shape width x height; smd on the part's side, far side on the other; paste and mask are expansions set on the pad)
0201_033L [mm] "0201"
  rect 0.36x0.32 smd mask+0: 1(-0.28,0) 2(0.28,0)
0402_070 [mil] "SMD, 2-Leads, Body 1.2x0.7mm, Height 0.7mm"
  rect 15x24 smd: 1(-20,0) 2(20,0)
0402L [mm] "0402 from SM-752 data"
  rect 0.6x0.5 smd: 1(-0.5,0) 2(0.5,0)
0603L [mm] "0603 from SM-752 data"
  rect 0.8x0.85 smd: 1(-0.7,0) 2(0.7,0)
  silkscreen extent -0.07,-0.33 0.07,0.33
0805L [mm] "0805 from SM-752 data"
  rect 1.1x1.4 smd: 1(-0.75,0) 2(0.75,0)
1206_180L [mm] "1206_180"
  rect 1.1x1.75 smd: 1(-1.35,0) 2(1.35,0)
  silkscreen extent -0.4,-0.78 0.4,0.78
1206L [mm] "1206 from SM-752 data"
  rect 1.1x1.75 smd: 1(-1.35,0) 2(1.35,0)
  silkscreen extent -0.4,-0.78 0.4,0.78
1210_270L [mm] "1210"
  rect 1.1x2.6 smd: 1(-1.35,0) 2(1.35,0)
  silkscreen extent -0.4,-1.2 0.4,1.2
1812_254 [mm] "SMD, 2-Leads, Body 4.8x3.4mm"
  rect 1.6x3.4 smd: 1(-2,0) 2(2,0)
  silkscreen extent -0.8,-1.7 0.8,1.7
2220_250L [mm] "2220"
  rect 1.4x5.2 smd: 1(-2.5,0) 2(2.5,0)
  silkscreen extent -1.4,-2.5 1.4,2.5
2512L [mm] "Chip Resistor, Body 6.3x3.2mm, IPC High Density"
  rect 1.1x3.3 smd: 1(-2.85,0) 2(2.85,0)
  silkscreen extent -1.9,-1.55 1.9,1.55
Bourns_3352T [mm] "TH, 3-Leads, Body 9.53x8.89mm, Pitch 2.54mm"
  rect 1.35x1.35 hole 0.85: 1(-2.54,0)
  round 1.35 hole 0.85: 2(0,0) 3(2.54,0)
  silkscreen extent -4.44,-2.6 4.44,7.31
Chemi-Con_1250x2000 [mm] "TH, 2-Leads, Dia 12.5mm, Lead Sapcing 5mm"
  rect 1.35x1.35 hole 0.85: 1(-2.5,0)
  round 1.35 hole 0.85: 2(2.5,0)
  silkscreen extent -6.5,-6.5 6.5,6.5
Diode_0603 [mm] "Based on Bourns recommended land pattern Rev 10/09"
  rect 0.7x1 smd: 1(-0.65,0) 2(0.65,0)
  silkscreen extent -1.22,-0.72 0.9,0.72
DRV0006A [mm] "SON, 6-Leads, Body 2x2mm, Pitch 0.65mm, Thermal Pad 1.6x1mm, TI Recommended"
  rrect33% 0.45x0.3 smd: 1(-0.975,0.65) 2(-0.975,0) 3(-0.975,-0.65) 4(0.975,-0.65) 5(0.975,0) 6(0.975,0.65)
  rrect14% 1x0.7 on Top Paste: 7(0,0.45) 7(0,-0.45)
  rrect10% 1x1.6 smd paste-0.5: 7(0,0)
  silkscreen extent -1.05,-1.2 1.05,1.2
FP-BLM18PG331SH1_0603-Recommended_Land_Pattern [mm]
  rrect15% 0.65x0.7 smd paste+0 mask+0: 1(-0.675,0) 2(0.675,0)
FP-SQJ850EP-T1-GE3_PowerPAK-SO-8L-Single-MFG [mm]
  rrect24% 0.41x0.82 smd paste+0 mask+0: 1(-1.905,-2.715) 2(-0.635,-2.715) 3(0.635,-2.715) 4(1.905,-2.715)
  round 3.655 smd paste+0 mask+0: 5(0,1.061)
  silkscreen extent -3.05,-3.81 3.05,2.78
Harwin_D3082-05 [mm] "Shorting Plug, 10.16mm spacing, TH"
  round 1.8 hole 1.3: 1(-5.08,0) 2(5.08,0)
  silkscreen extent -3.9,-0.53 3.9,0.53
Keystone5000 [mil] "For Keystone 500x miniature loop terminals"
  round 80 hole 40: 1(0,0)
  silkscreen extent -52,-52 52,52
Keystone5002 [mil] "For Keystone 500x miniature loop terminals"
  round 80 hole 40: 1(0,0)
  silkscreen extent -52,-52 52,52
Keystone5005 [mil] "Keystone Compact loops"
  round 87 hole 63: 1(0,0)
  silkscreen extent -70,-70 70,70
Keystone_1902C [mil] "Hex Standoff, 4-40 threaded, nylon"
  round 1 on Mech3: 0(0,0)
LED_LTST-C170_Red [mm] "LITE-ON"
  rect 1.2x1.2 smd: 1(-1.05,0) 2(1.05,0)
  silkscreen extent -1.6,-1 2.2,1
LTST-C170KFKT_Orange [mm] "LITE-ON"
  rect 1.2x1.2 smd: 1(-1.05,0) 2(1.05,0)
  silkscreen extent -1.6,-1 2.2,1
LTST-C170KGKT_Green [mm] "LITE-ON"
  rect 1.2x1.2 smd: 1(-1.05,0) 2(1.05,0)
  silkscreen extent -1.6,-1 2.2,1
Net-Tie_10mil [mil] "10mil net tie, no solder mask opening, no solder paste"
  rect 10x10 smd paste-5 mask+0: 1(-10,0) 2(10,0)
"NY PMS 440 0025 PH" [mm] "4-40 nylon screw and mounting hole"
  round 8 hole 3.2: 1(0,0)
On-Shore_OSTT7032150 [mm] "Terminal Block, 3x1, 9.52mm, TH"
  rect 2.1x2.1 hole 1.6: 1(-9.52,0)
  round 2.1 hole 1.6: 2(0,0) 3(9.52,0)
  silkscreen extent -14.78,-8 14.28,5
PHP0048G_N [mm] "QFP, 48-Leads, Body 7x7mm, Pitch 0.5mm, Thermal Pad 5.17X5.17mm, IPC Medium Density"
  rrect33% 1.45x0.3 smd: 1(-4.225,2.75) 2(-4.225,2.25) 3(-4.225,1.75) 4(-4.225,1.25) 5(-4.225,0.75) 6(-4.225,0.25) 7(-4.225,-0.25) 8(-4.225,-0.75) 9(-4.225,-1.25) 10(-4.225,-1.75) 11(-4.225,-2.25) 12(-4.225,-2.75) 25(4.225,-2.75) 26(4.225,-2.25) 27(4.225,-1.75) 28(4.225,-1.25) 29(4.225,-0.75) 30(4.225,-0.25) 31(4.225,0.25) 32(4.225,0.75) 33(4.225,1.25) 34(4.225,1.75) 35(4.225,2.25) 36(4.225,2.75)
  rrect33% 0.3x1.45 smd: 13(-2.75,-4.225) 14(-2.25,-4.225) 15(-1.75,-4.225) 16(-1.25,-4.225) 17(-0.75,-4.225) 18(-0.25,-4.225) 19(0.25,-4.225) 20(0.75,-4.225) 21(1.25,-4.225) 22(1.75,-4.225) 23(2.25,-4.225) 24(2.75,-4.225) 37(2.75,4.225) 38(2.25,4.225) 39(1.75,4.225) 40(1.25,4.225) 41(0.75,4.225) 42(0.25,4.225) 43(-0.25,4.225) 44(-0.75,4.225) 45(-1.25,4.225) 46(-1.75,4.225) 47(-2.25,4.225) 48(-2.75,4.225)
  rrect2% 5.17x5.17 on Top Paste: 49(0,0)
  rrect3% 6x6 smd paste-3 mask+0: 49(0,0)
  rrect2% 5.17x5.17 on Top Solder: 49(0,0)
  silkscreen extent -3.6,-3.6 3.6,3.6
RNX0012A [mm]
  rrect57% 0.7x0.35 smd paste-0.05 mask+0: 1(-0.9,1.125) 2(-0.9,0.475) 10(0.9,0.475) 11(0.9,1.125)
  rrect40% 0.6x0.25 smd: 3(-0.9,-0.175) 4(-0.9,-0.675) 8(0.9,-0.7) 9(0.9,-0.2)
  rrect40% 0.25x0.6 smd: 5(-0.5,-1.4) 6(0,-1.4) 7(0.5,-1.4)
  rrect40% 0.25x0.812 on Top Paste: 12(0,0.28) 12(0,1.295)
  rrect57% 0.35x1.925 smd paste-0.175 mask+0: 12(0,0.788)
  silkscreen extent -1.15,-1.65 1.15,1.65
RSH0056D [mm]
  oval 0.7x0.2 smd mask+0: 1(-3.35,2.6) 2(-3.35,2.2) 3(-3.35,1.8) 4(-3.35,1.4) 5(-3.35,1) 6(-3.35,0.6) 7(-3.35,0.2) 8(-3.35,-0.2) 9(-3.35,-0.6) 10(-3.35,-1) 11(-3.35,-1.4) 12(-3.35,-1.8) 13(-3.35,-2.2) 14(-3.35,-2.6) 29(3.35,-2.6) 30(3.35,-2.2) 31(3.35,-1.8) 32(3.35,-1.4) 33(3.35,-1) 34(3.35,-0.6) 35(3.35,-0.2) 36(3.35,0.2) 37(3.35,0.6) 38(3.35,1) 39(3.35,1.4) 40(3.35,1.8) 41(3.35,2.2) 42(3.35,2.6)
  oval 0.2x0.7 smd mask+0: 15(-2.6,-3.35) 16(-2.2,-3.35) 17(-1.8,-3.35) 18(-1.4,-3.35) 19(-1,-3.35) 20(-0.6,-3.35) 21(-0.2,-3.35) 22(0.2,-3.35) 23(0.6,-3.35) 24(1,-3.35) 25(1.4,-3.35) 26(1.8,-3.35) 27(2.2,-3.35) 28(2.6,-3.35) 43(2.6,3.35) 44(2.2,3.35) 45(1.8,3.35) 46(1.4,3.35) 47(1,3.35) 48(0.6,3.35) 49(0.2,3.35) 50(-0.2,3.35) 51(-0.6,3.35) 52(-1,3.35) 53(-1.4,3.35) 54(-1.8,3.35) 55(-2.2,3.35) 56(-2.6,3.35)
  rect 5.3x5.3 smd paste-2.7 mask+0: 57(0,0)
  silkscreen extent -3.7,-3.7 3.7,3.7
SO-8FL [mm] "ON SEMICONDUCTOR, DFN5 5x6, 1.27P, CASE 488AA"
  rect 1x0.75 smd: 1(-2.795,1.905) 2(-2.795,0.635) 3(-2.795,-0.635) 4(-2.795,-1.905)
  rect 4.055x4.56 smd: 5(0.698,0)
  Top Layer region: 3.2,-2.28 3.2,-1.53 2.65,-1.53 2.65,-2.28
  Top Layer region: 3.2,1.53 3.2,2.28 2.655,2.28 2.655,1.53
  silkscreen extent -3.1,-2.6 3.1,2.9
SOT-23L [mm] "SOT23, 3-Leads, Body 2.9x1.3mm, Pitch 0.95mm, Lead Span 2.5mm, IPC High Density"
  rrect50% 0.8x0.6 smd: 1(-1.1,0.95) 2(-1.1,-0.95) 3(1.1,0)
  silkscreen extent -1.5,-1.5 0.7,1.5
SRP1250 [mm] "BOURNS"
  rect 4x4.5 smd: 1(-5.5,0) 2(5.5,0)
  silkscreen extent -7,-6.8 7,6.8
SRU1028A [mm] "Bourns recommended land pattern"
  rrect6% 1.8x4 smd: 1(-4.5,0) 2(4.5,0)
  silkscreen extent -5.15,-5.3 5.13,5.25
SW_1138K9-9F9F1125 [mm] "SMT, 4-Leads, Body 6x6mm"
  rect 2x1 smd: 1(-4.5,2.25) 2(4.5,2.25) 3(-4.5,-2.25) 4(4.5,-2.25)
  silkscreen extent -3.1,-3.1 3.1,3.4
SW_SKRKAEE010 [mm] "Alps recommended land pattern"
  rect 0.8x2 smd: 1(-2.1,0) 2(2.1,0)
  silkscreen extent -1.9,-1.44 1.92,1.44
TERM_BLK_OSTT7022150 [mm]
  rect 2.54x2.54 hole 1.6: 1(0,0)
  round 2.54 hole 1.6: 2(9.525,0)
  silkscreen extent -5.74,-8.28 14.63,4.83
TNPW0603 [mm] "Vishay"
  rect 0.5x0.9 smd: 1(-0.75,0) 2(0.75,0)
  silkscreen extent -0.2,-0.6 0.2,0.6
TO-277A [mm] "Vishay"
  rect 1.4x1.27 smd: 1(-1.04,1.83) 2(1.04,1.83)
  rect 4.72x4.8 smd: 3(0,-1.883)
  silkscreen extent -2.7,1.45 -2.4,1.75
TSW-107-07-X-D [mm] "Samtec 100mil, 2x7, 230 mil above insulator"
  rrect6% 1.65x1.65 hole 1.016: 1(-7.62,-1.27)
  round 1.65 hole 1.016: 2(-7.62,1.27) 3(-5.08,-1.27) 4(-5.08,1.27) 5(-2.54,-1.27) 6(-2.54,1.27) 7(0,-1.27) 8(0,1.27) 9(2.54,-1.27) 10(2.54,1.27) 11(5.08,-1.27) 12(5.08,1.27) 13(7.62,-1.27) 14(7.62,1.27)
  silkscreen extent -9.92,-2.52 9.14,2.5

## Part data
3.3V 6V: library part CMP-0055137-1, "Test Point, Miniature, Red, TH"
AI1 AI2 AI3: library part CMP-0055139-1, "Test Point, Miniature, White, TH"
C1 C2 C3 C4 C5 C6: library part CMP-0007468-5, "CAP, CERM, 0.01 uF, 100 V, +/- 10%, X7R, 0603"
C7 C13 C14: library part CMP-0006726-1, "CAP, CERM, 0.01 uF, 100 V, +/- 5%, X7R, 0603"
C8 C12 C16: library part CMP-0007980-1, "CAP, CERM, 1 uF, 100 V, +/- 10%, X7S, AEC-Q200 Grade 1, 0805"
C9 C10 C11: library part CMP-0009912-1, "CAP, AL, 330 uF, 63 V, +/- 20%, AEC-Q200 Grade 2, TH"
C15 C17 C18: library part CMP-0009399-1, "CAP, CERM, 22 uF, 16 V, +/- 20%, X7R, AEC-Q200 Grade 1, 1812"
C19: library part CMP-0008779-1, "CAP, CERM, 1 uF, 100 V, +/- 10%, X7R, AEC-Q200 Grade 1, 1206"
C20: library part CMP-0009660-1, "CAP, CERM, 100 pF, 25 V, +/- 10%, X7R, AEC-Q200 Grade 1, 0201"
C21 C24: library part CMP-0007086-1, "CAP, CERM, 0.022 uF, 100 V, +/- 10%, X7R, AEC-Q200 Grade 1, 0603"
C22 C25 C26: library part CMP-0007376-4, "CAP, CERM, 1000 pF, 16 V, +/- 10%, X7R, 0603"
C23 C27 C30: library part CMP-0007387-4, "CAP, CERM, 2200 pF, 16 V, +/- 10%, X7R, 0603"
C28: library part CMP-0009413-1, "CAP, CERM, 4.7 uF, 100 V, +/- 10%, X7R, AEC-Q200 Grade 1,"
C29 C45: library part CMP-0008815-2, "CAP, CERM, 1 uF, 100 V, +/- 10%, X7R, AEC-Q200 Grade 1, 1206"
C31 C46: library part CMP-0007099-4, "CAP, CERM, 0.1 uF, 100 V, +/- 10%, X7S, AEC-Q200 Grade 1, 0603"
C32 C48: library part CMP-0007082-4, "CAP, CERM, 0.01 uF, 100 V, +/- 10%, X7R, AEC-Q200 Grade 1, 0603"
C33 C49: library part CMP-0007081-4, "CAP, CERM, 1000 pF, 100 V, +/- 10%, X7R, AEC-Q200 Grade 1, 0603"
C34: library part CMP-0007359-4, "CAP, CERM, 0.1 uF, 6.3 V, +/- 10%, X7R, 0603"
C35: library part CMP-0007139-1, "CAP, CERM, 1 uF, 25 V, +/- 10%, X7R, AEC-Q200 Grade 1, 0603"
C36: library part CMP-0064935-1, "CAP, CERM, 0.1 uF, 100 V,+/- 10%, X7R, AEC-Q200 Grade 1, 0603"
C37: library part CMP-0009912-2, "CAP, AL, 330 uF, 63 V, +/- 20%, AEC-Q200 Grade 2, TH"
C38: library part CMP-0009230-2, "CAP, CERM, 4.7 uF, 80 V, +/- 10%, X7R, 1210"
C39: library part CMP-0007970-1, "CAP, CERM, 0.047 uF, 100 V, +/- 10%, X7R, AEC-Q200 Grade 1, 0805"
C40: library part CMP-0086190-1, "CAP, CERM, 1 µF, 6.3 V,+/- 10%, X7R, AEC-Q200 Grade 1, 0603"
C41: library part CMP-0007106-1, "CAP, CERM, 0.1 uF, 16 V, +/- 10%, X7R, AEC-Q200 Grade 1, 0603"
C42: library part CMP-0006857-4, "CAP, CERM, 0.1 uF, 16 V, +/- 5%, X7R, 0603"
C43 C44 C50 C51 C56: library part CMP-0007370-1, "CAP, CERM, 2.2 uF, 10 V, +/- 10%, X7R, 0603"
C47: library part CMP-0086250-1, "CAP, CERM, 2.2 µF, 10 V,+/- 10%, X7S, AEC-Q200 Grade 1, 0402"
C52 C53 C54 C55: library part CMP-0006237-1, "CAP, CERM, 0.1 uF, 16 V, +/- 10%, X7R, AEC-Q200 Grade 1, 0402"
D1 D13 D14: library part CMP-0028876-1, "Diode, Schottky, 100 V, 20 A, AEC-Q101, TO-277A"
D2 D3 D4: library part CMP-0002888-1, "LED, Green, SMD"
D5 D6 D8 D9 D10 D11: library part CMP-0002890-1, "LED, Orange, SMD"
D7: library part CMP-0002829-1, "LED, Red, SMD"
D12 D15 D16: library part CMP-0029009-2, "Diode, Switching, 90 V, 0.1 A, 0603 Diode"
FB1 FB2 FB3: library part CMP-0087073-2, "Ferrite Beads 330 Ohm 25%"
GND1 GND2 GND3: library part CMP-0075110-1, "1mm Uninsulated Shorting Plug, 10.16mm spacing, TH"
H1 H2 H6: library part CMP-0074912-1, "Terminal Block, 30A, 9.52mm (.375) Pitch, 2-Pos, TH"
H3 H4 H7 H8: library part CMP-0003617-1, "Machine Screw, Round, #4-40 x 1/4, Nylon, Philips panhead"
H5: library part CMP-0075120-1, "Terminal Block, 3x1, 9.52mm, TH"
H9 H10 H11 H12: library part CMP-0003610-1
J1: library part CMP-0075415-1, "Header, 100mil, 7x2, Gold, TH"
L1: library part CMP-0058027-1, "Inductor, Shielded Drum Core, Ferrite, 47 uH, 1.1 A, 0.23 ohm, AEC-Q200 Grade 1, SMD"
L2: library part CMP-0056889-1, "Inductor, Powdered Iron, 1 uH, 29 A, 0.0025 ohm, SMD"
NT1 NT2 NT3 NT4 NT5 NT6 NT7 NT8 NT9 NT10 NT11 NT12 NT13 NT14 NT15 NT16 NT17: library part CMP-0078142-3, "Single point connection between nets."
Q1 Q2 Q3 Q4 Q5 Q6: library part CMP-0086718-1, "Single N-Channel 60 V 0.023 Ohms Surface Mount Power Mosfet - PowerPAK-SO-8L"
Q7: library part CMP-0084694-1, "MOSFET, N-CH, 80 V, 123 A, AEC-Q101, SO-8FL"
Q8: library part CMP-0000467-1, "Transistor, NPN, 80 V, 1.5 A, AEC-Q101, SOT-23"
R1 R2 R4 R8 R12 R13: library part CMP-0025700-4, "RES, 100, 5%, 0.1 W, AEC-Q200 Grade 0, 0603"
R3 R5 R9 R10 R31: library part CMP-0022655-3, "RES, 93.1 k, 1%, 0.1 W, 0603"
R6 R7 R11: library part CMP-0015837-1, "RES, 0.005, 1%, 2 W, 2512"
R14 R33 R34 R35 R39 R40 R41 R42: library part CMP-0025785-4, "RES, 330, 5%, 0.1 W, AEC-Q200 Grade 0, 0603"
R15: library part CMP-0023554-1, "RES, 470, 0.1%, 0.1 W, 0603"
R16: library part CMP-0025694-1, "RES, 5.11 k, 0.1%, 0.1 W, AEC-Q200 Grade 1, 0603"
R17: library part CMP-0016779-3, "RES, 20.0 k, 1%, 0.25 W, AEC-Q200 Grade 0, 1206"
R18: library part CMP-0018819-1, "RES, 100 k, 0.1%, 0.25 W, AEC-Q200 Grade 1, 1206"
R19 R30 R37 R48 R49 R50 R52 R53 R54 R55 R56 R57 R58 R59 R60 R61: library part CMP-0022438-1, "RES, 47.0 k, 1%, 0.1 W, AEC-Q200 Grade 0, 0603"
R20 R21 R22 R23 R26 R29 R36: library part CMP-0025697-4, "RES, 0, 5%, 0.1 W, AEC-Q200 Grade 0, 0603"
R24 R25 R27: library part CMP-0025829-1, "RES, 56, 5%, 0.1 W, 0603"
R28 R38 R43: library part CMP-0025701-4, "RES, 10 k, 5%, 0.1 W, AEC-Q200 Grade 0, 0603"
R32 R44 R45 R46 R47: library part CMP-0021989-3, "RES, 4.99 k, 1%, 0.1 W, 0603"
R51: library part CMP-0001777-1, "Trimming Potentiometer, 50K, 0.5W, TH"
S1 S2 S3 S4 S5: library part CMP-0002279-1, "Switch, SPST, 0.05A, 12V, SMD"
S6: library part CMP-0002113-1, "Switch, Push Button, SMD"
U1: library part CMP-0860463-1, "Automotive 150-mA high-voltage ultra-low-IQ low-dropout (LDO) linear regulator, DRV0006A (WSON-6)"
U2: library part CMP-0077180-1, "SIMPLE SWITCHER 4.2 V to 60 V 0.6 A Synchronous Step-Down Converter, RNX0012A (VQFN-HR-12)"
U3: library part CMP-0065203-5, "Automotive 5.5 to 60-V Three-Phase Smart Gate Driver With Three Integrated Current-Shunt Amplifiers, PHP0048G (HTQFP-48)"
U4: library part CMP-0067520-1, "Piccolo Microcontroller, RSH0056D (VQFN-56)"
VM: library part CMP-0055142-1, "Test Point, Compact, Red, TH"

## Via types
v1: diameter 25, hole 10, Top Layer to Bottom Layer, tented both sides, 315 vias
v2: diameter 20, hole 10, Top Layer to Bottom Layer, 173 vias
v3: diameter 25, hole 15, Top Layer to Bottom Layer, 106 vias
v4: diameter 19.68, hole 7.87, Top Layer to Bottom Layer, 32 vias
v5: diameter 19.68, hole 7.87, Top Layer to Bottom Layer, tented both sides, 16 vias

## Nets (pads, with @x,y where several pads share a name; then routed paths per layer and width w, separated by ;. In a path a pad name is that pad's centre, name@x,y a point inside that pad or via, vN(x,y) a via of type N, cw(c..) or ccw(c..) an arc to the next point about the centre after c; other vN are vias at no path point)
3.3V_LDO: 3.3V.1 C18.1 C34.1 C41.1 D2.1 D5.1 D6.1 D7.1 D8.1 D9.1 D10.1 D11.1 FB1.1 FB2.1 FB3.1 J1.5 NT17.1 R19.2 R28.2 R30.2 R37.2 R48.2 R49.2 R50.2 R51.1 U1.6 U3.30 | length 6455.4
  Top Layer w8: v2(340,1920) 372.51,1887.49 R19.2@385,1887.49 ; R48.2@1280,3597.56 v2(1347.56,3597.56) ; v2(1590,2940) FB1.1@1633.43,2940 ; v2(1750,2690) C41.1@1800,2690 1780,2670 NT17.1@1780,2612.76 ; U3.30@1896.34,2372.91 1896.34,2372 2028,2372 2047.24,2352.76 2082.44,2352.76 C34.1@2082.44,2412.76
  Top Layer w10: v2(320,3590) 340,3610 387.56,3610 R49.2@390,3607.56 390,3675.12 R50.2@444.88,3730 490,3684.88 564.88,3684.88 620,3740 R51.1@620,3890 ; v2(330,2500) 360,2470 R30.2@370,2470 669.86,2470 D5.1@761.37,2561.51 D6.1@901.37,2561.51 D7.1@1041.37,2561.51 ; v2(330,3080) 369.06,3040.94 R37.2@370,3040.94 660.94,3040.94 D8.1@710,3090 D9.1@843.33,3090 D10.1@976.67,3090 D11.1@1110,3090 ; v3(1460,3670) 1470,3670 1490,3650 FB3.1@1490,3606.57 ; FB2.1@1986.57,3480 1986.57,3516.57 v3(2010,3540) ; v2(2090,2470) 2092.44,2467.56 C34.1@2092.44,2412.76
  Top Layer w20: v2(2397.5,1972.5) 2460,2035 2586.26,2035 C18.1@2590,2038.74 ; 3.3V.1@2560,2230 2590,2200 C18.1@2590,2038.74 ; D2.1@3450,1371.34 2998.66,1371.34 2750,1620 2750,1940 2758.39,1948.39 2784.41,1948.39 2784.41,1985.59 2731.26,2038.74 C18.1@2590,2038.74
  POWER w10: v2(320,3590) 320,3090 v2(330,3080) v2(330,2500) 330,1930 v2(340,1920)
  other v2: 2337.5,1912.5 2397.5,1912.5 2337.5,1972.5
6V_BUCK: 6V.1 C15.1 C17.1 D3.1 D16.2 L1.2 R18.2 U1.1 U1.2 | length 1565.3
  Top Layer w10: v2(3010,1640) v2@3011.26,1638.74
  Top Layer w20: v2@3011.26,1638.74 C15.1@3150,1638.74
  POWER w20: v2(1540,1950) 2030,1950 2140,1840 2220,1760 v2(2820,1760)
  Bottom Layer w10: D16.2@1531.18,2000 D16.2@1540,1991.18
  Bottom Layer w20: D16.2@1531.18,2000 1531.18,1968.82 1540,1960 v2(1540,1950)
  other v2: 3470,1610 3470,1670 3470,1720 3280,1810 3340,1810 3280,1860
BST: C20.1 U2.4 | length 101.4
  Top Layer w8: C20.1@3010,2080 3010,2070 3026.57,2053.43 U2.4@3094.57,2053.43
CPH: C39.1 U3.2 | length 110.8
  Top Layer w8: C39.1@1510.47,2540 1510.47,2490.24 1529.37,2471.34 U3.2@1563.66,2471.34
CPL: C39.2 U3.1 | length 51.4
  Top Layer w8: U3.1@1563.66,2491.02 1563.66,2534.13 C39.2@1569.53,2540
DL_A: NT16.1 U3.8 | length 39
  Top Layer w8: 1526,2350 1529.23,2353.23 U3.8@1563.66,2353.23
DL_B: NT8.1 R58.1 R59.2 U3.17 | length 288.8
  Top Layer w10: 1660,2047 1660,2090 v2(1680,2110) 1700.47,2130.47 U3.17@1700.47,2216.42
  Bottom Layer w10: R58.1@1581.5,2120 1628.5,2120 1630,2118.5 1671.5,2118.5 v2(1680,2110)
DL_C: NT10.1 R55.1 R57.2 U3.22 | length 344.3
  Top Layer w10: U3.22@1798.9,2216.42 1798.9,2171.1 v2(1840,2130) 1900,2070 1900,2067
  Bottom Layer w10: v2(1840,2130) 1840,2070 1870,2040 1870,1991.5 R55.1@1868.5,1990
DVDD: C40.1 U3.39 | length 76.5
  Top Layer w8: U3.39@1798.9,2549.09 1798.9,2598.9 1812.44,2612.44 C40.1@1812.44,2620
